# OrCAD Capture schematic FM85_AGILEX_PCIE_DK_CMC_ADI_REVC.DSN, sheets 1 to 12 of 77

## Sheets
1 Title, Note, Rev. Hist: title: AgileX I-Series FPGA Dev Kit; rev: B; note: M17472       (M17471-100, M35170-100)
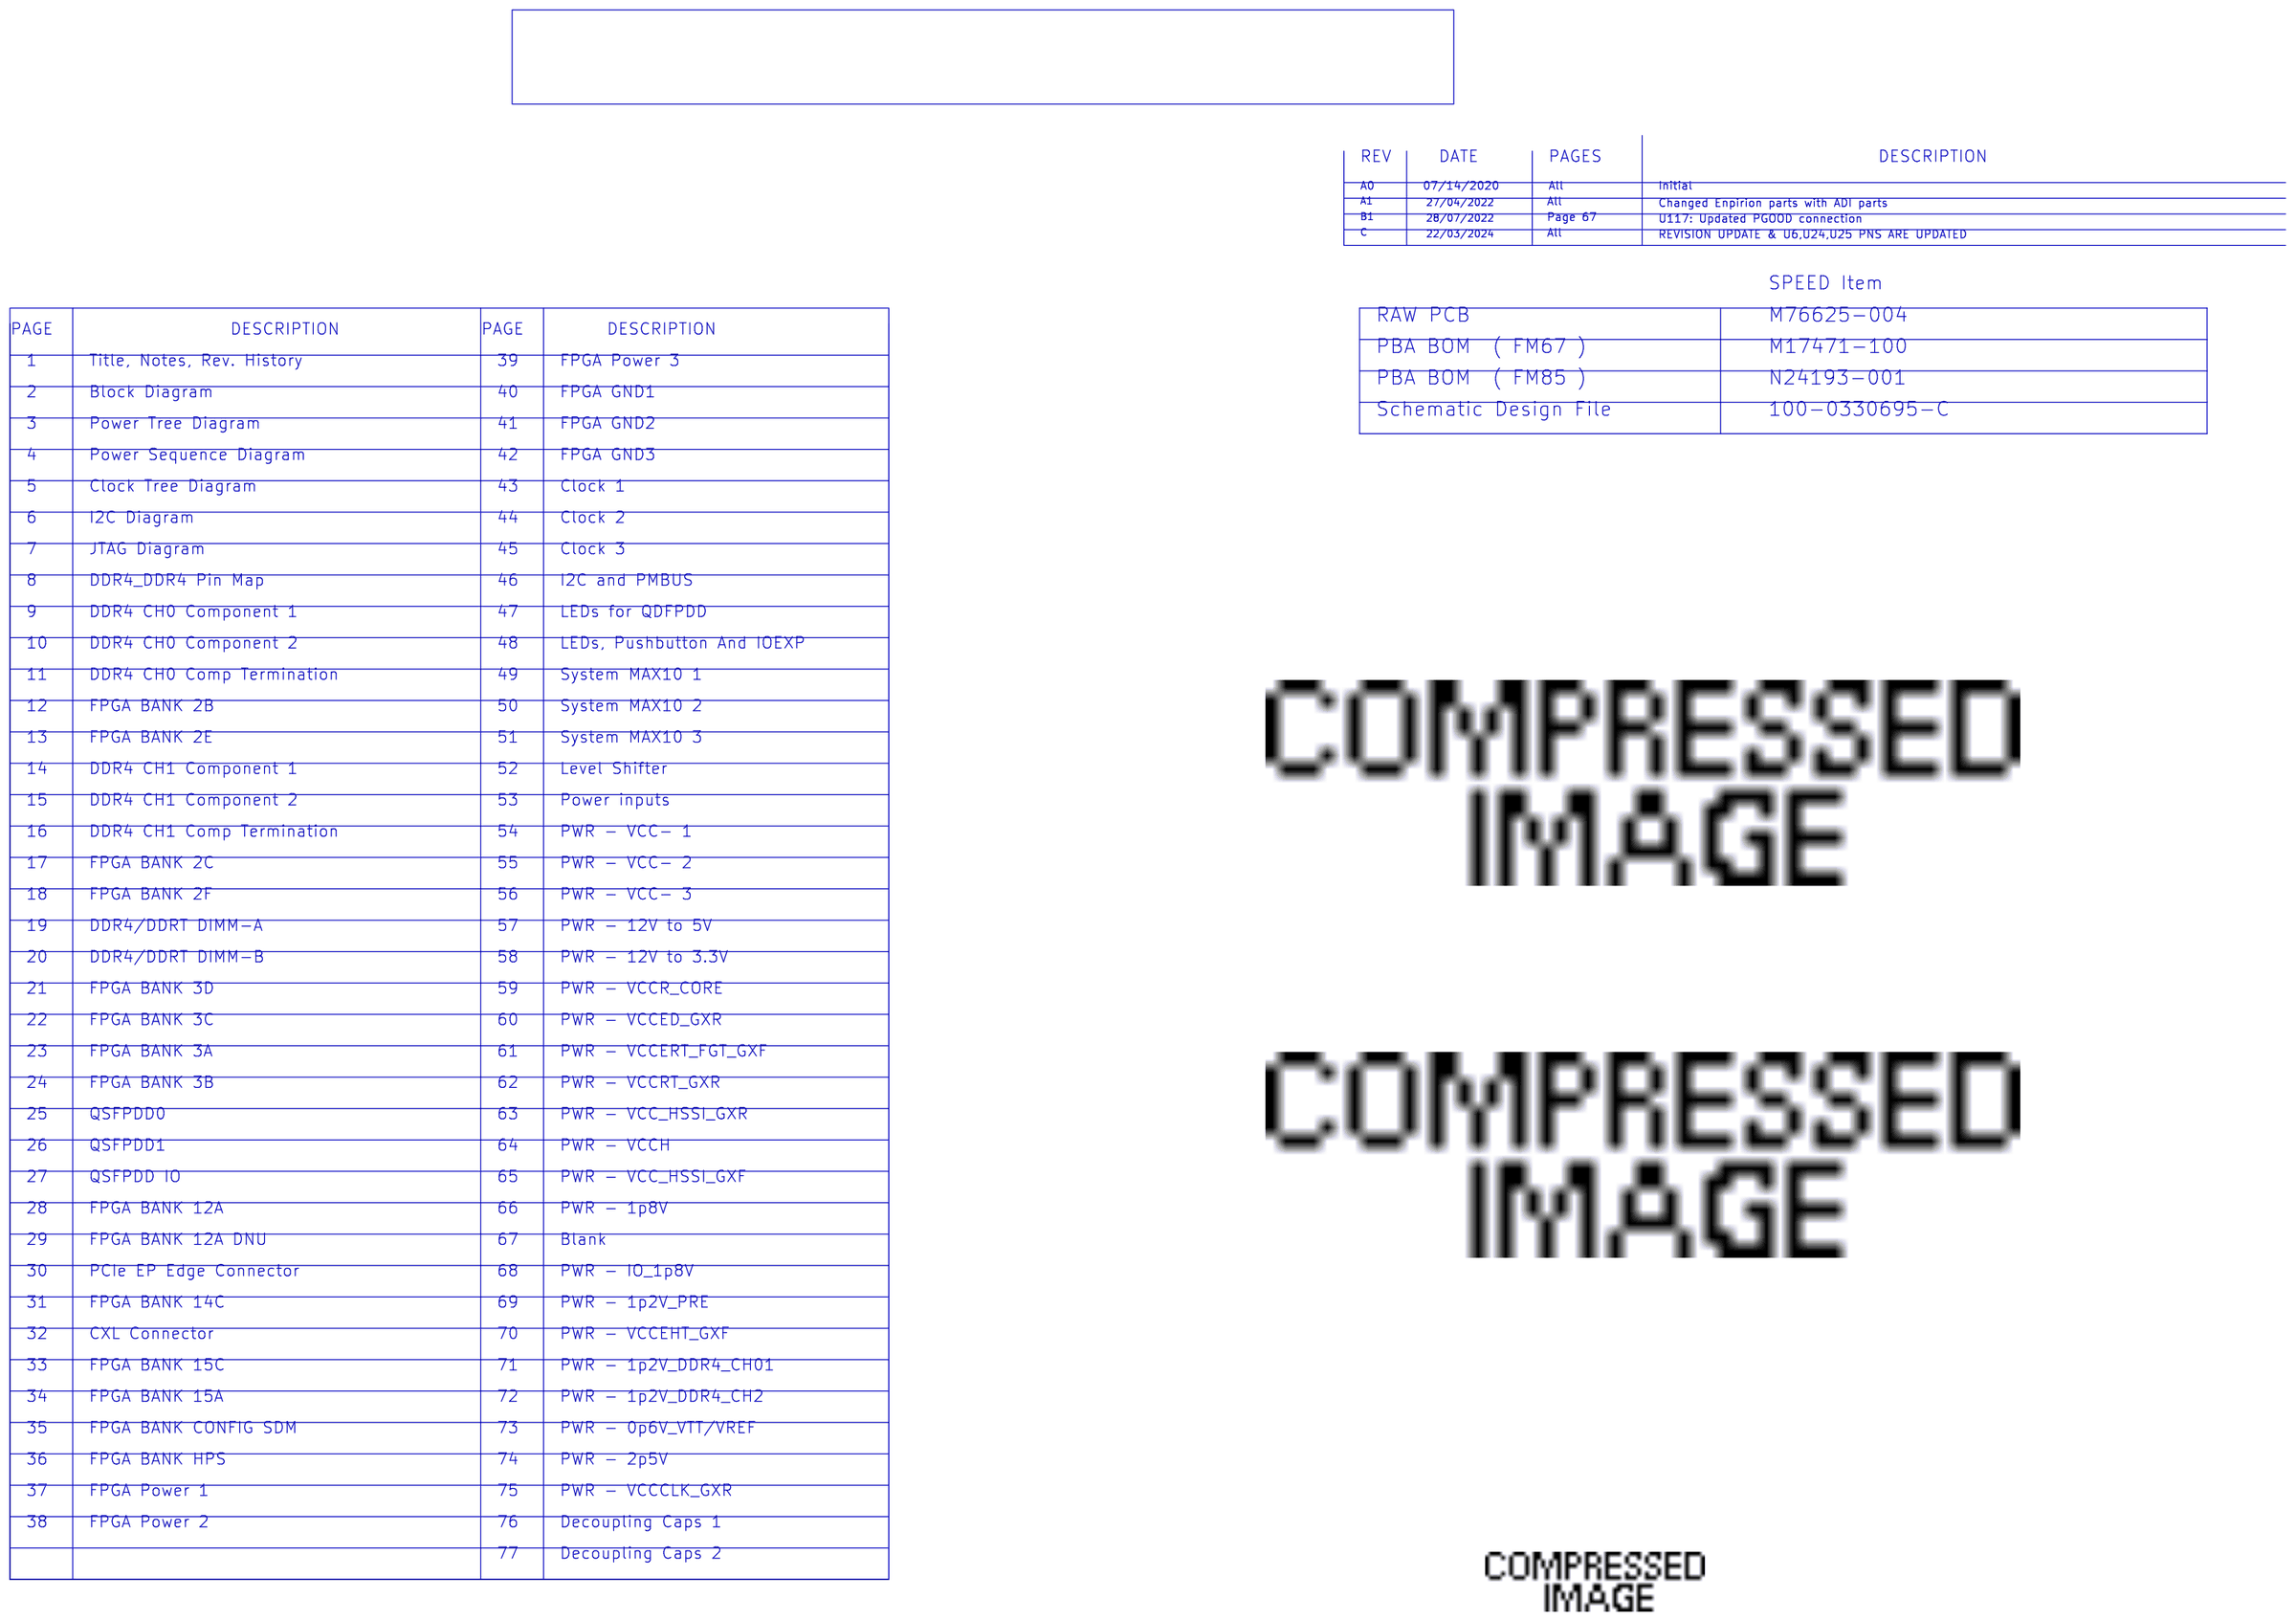
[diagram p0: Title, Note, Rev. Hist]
2 Block Diagram
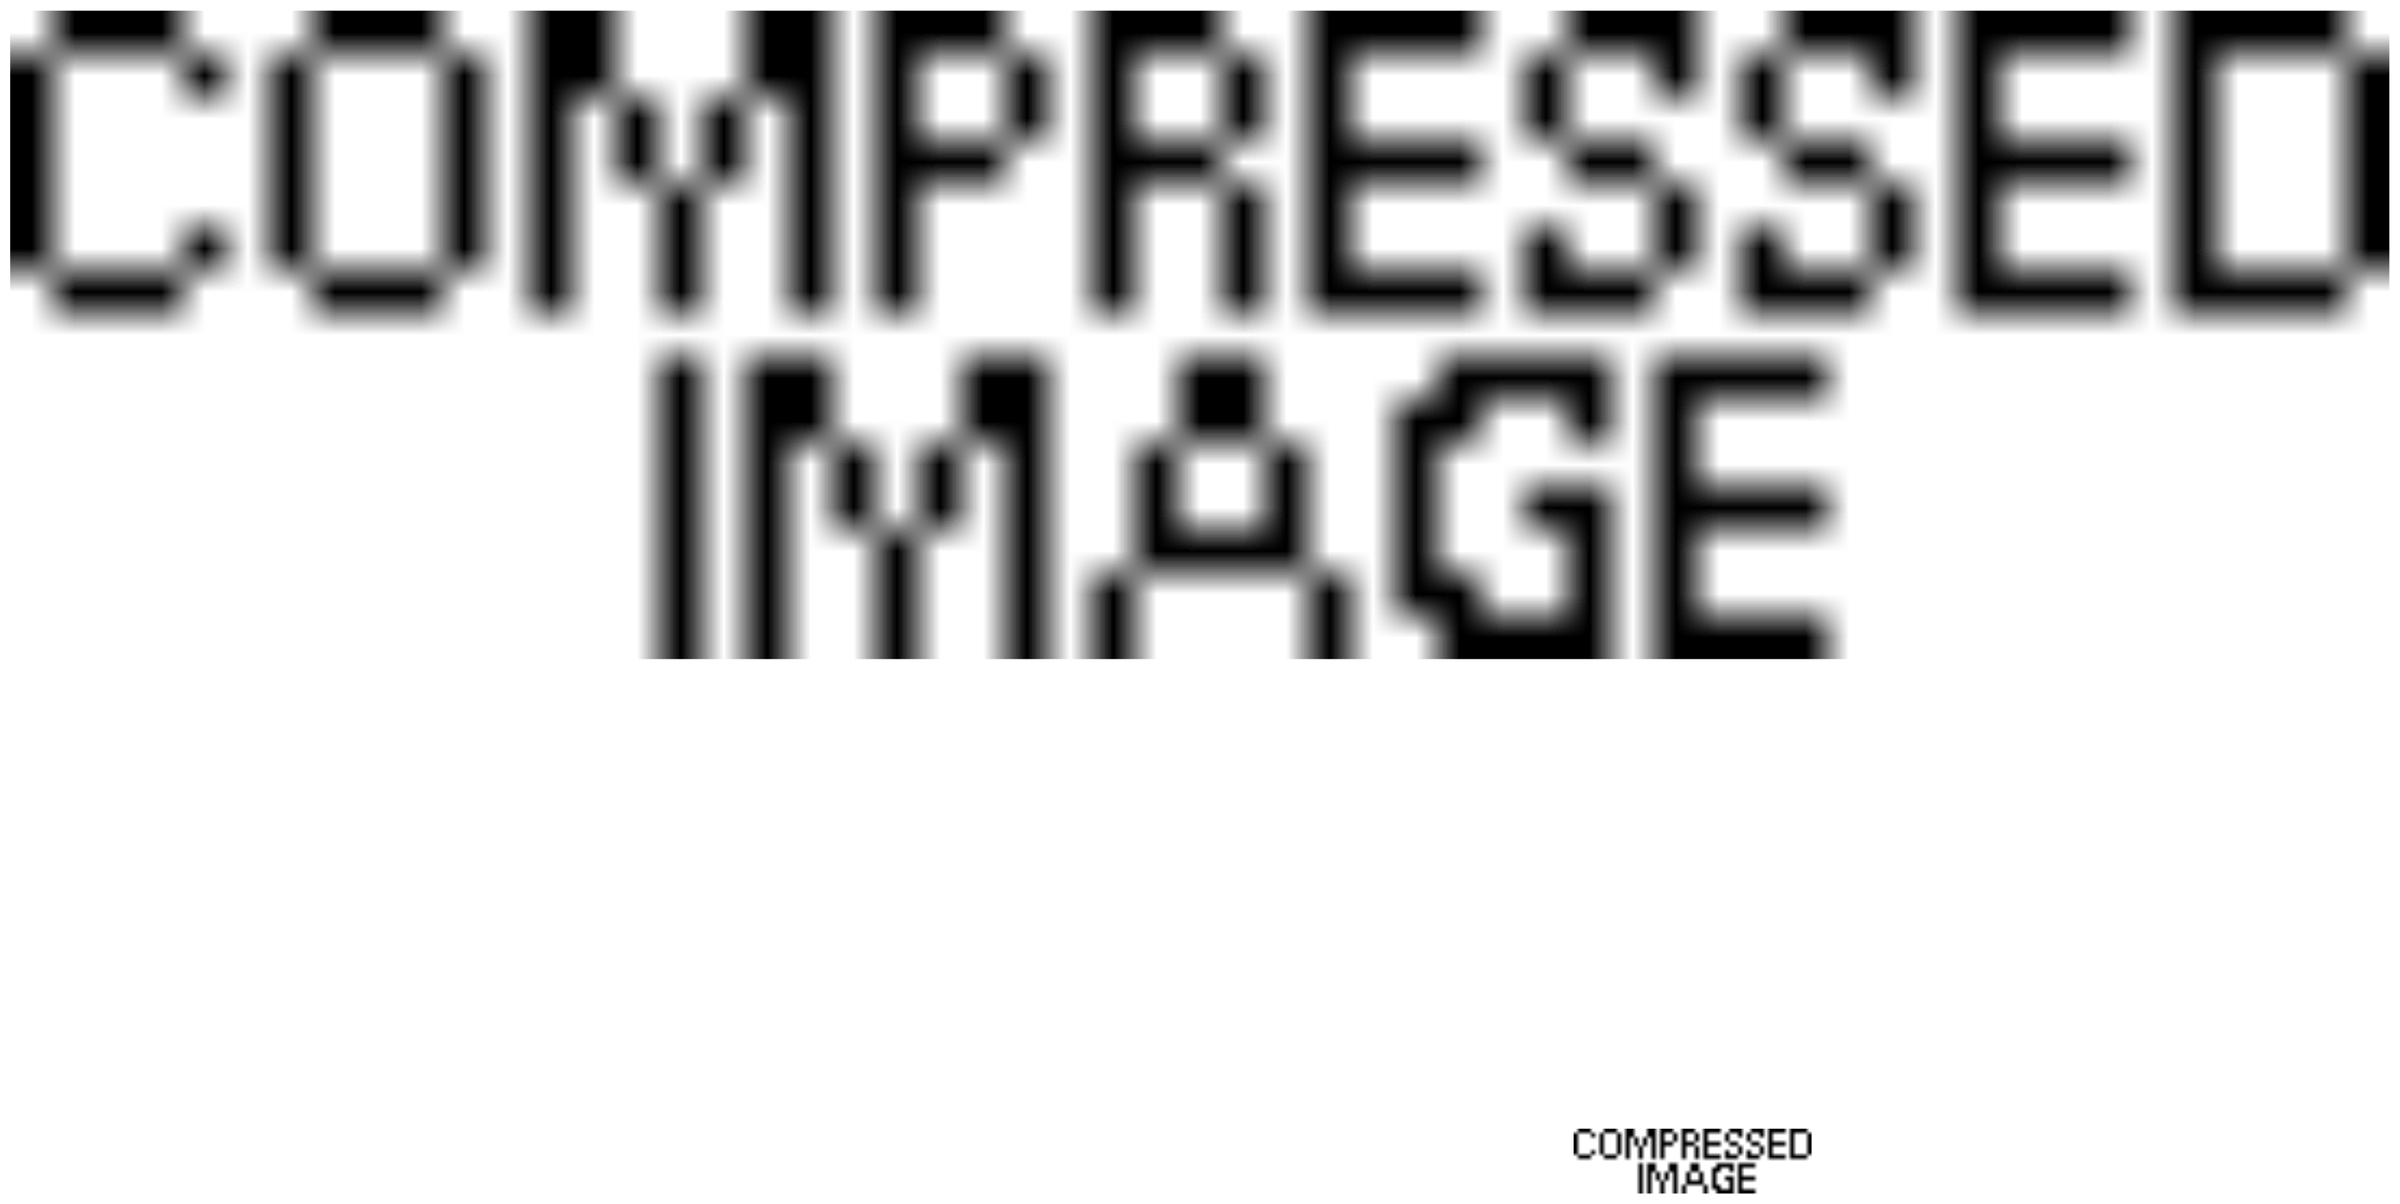
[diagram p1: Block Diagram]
3 Power Tree
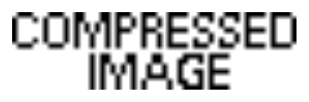
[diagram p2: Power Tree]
4 Power Sequence Diagram
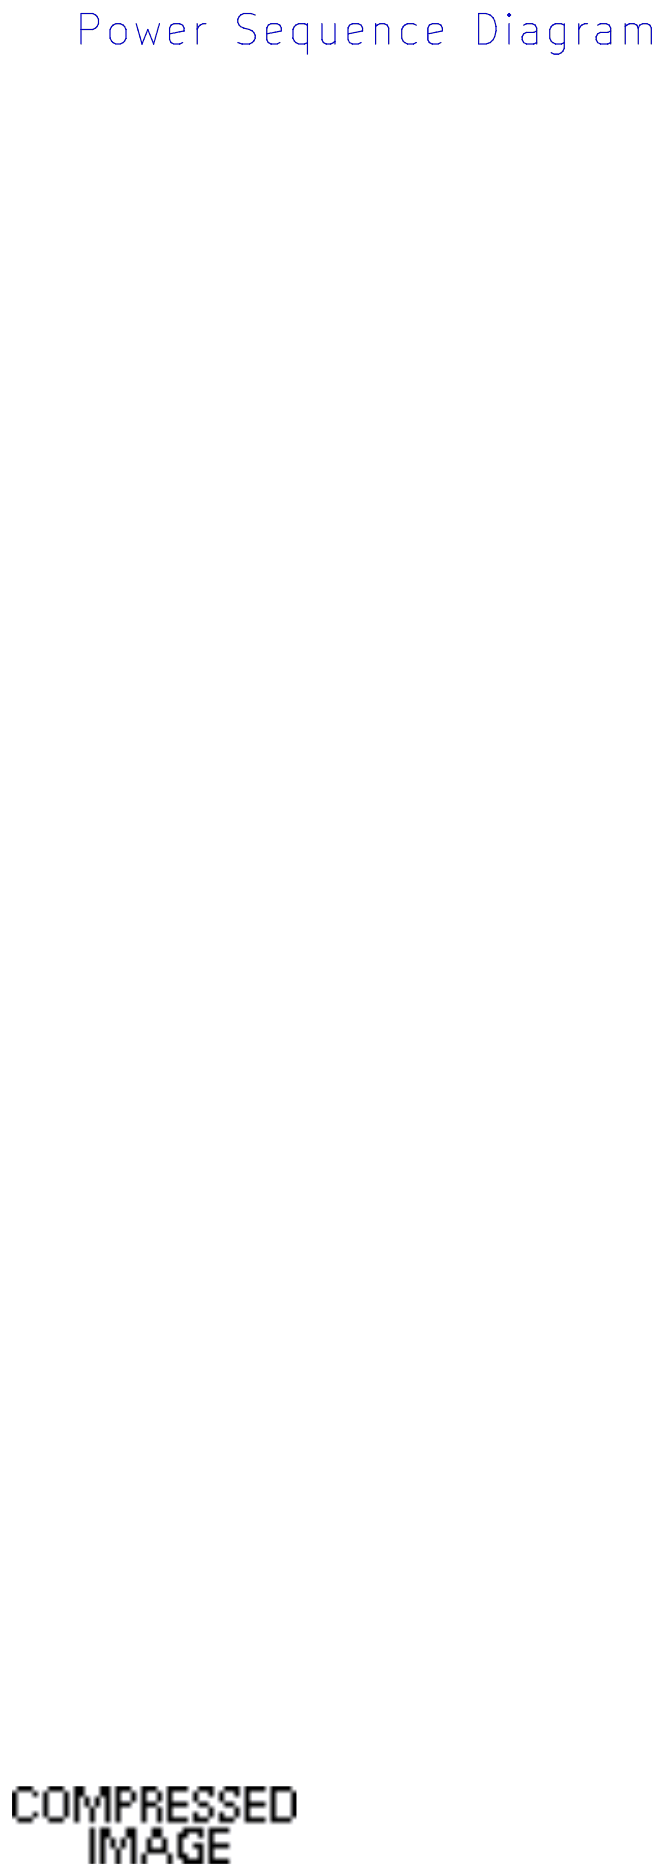
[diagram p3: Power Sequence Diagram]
5 Clock Tree Diagram
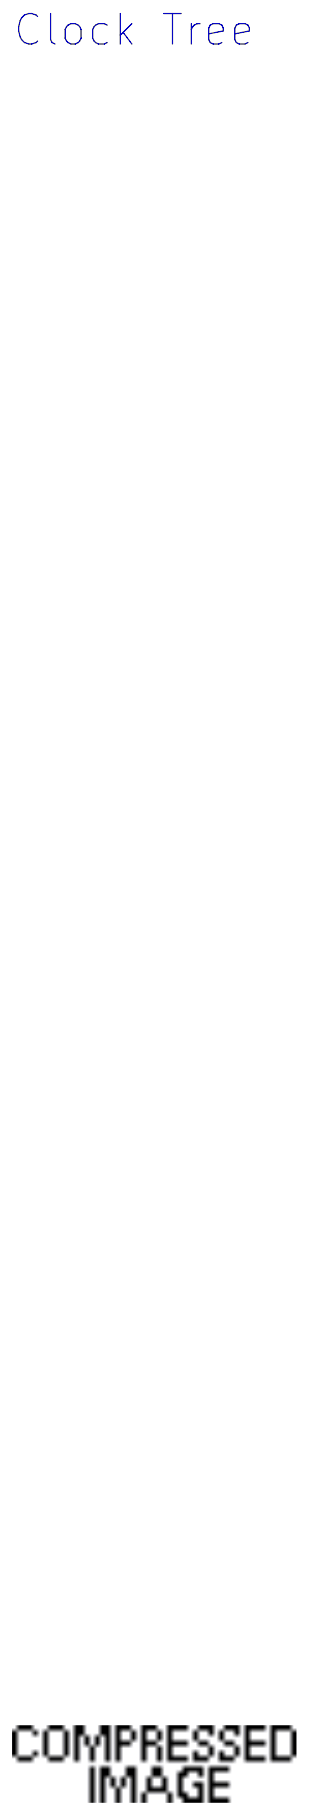
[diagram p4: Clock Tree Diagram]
6 I2C Diagram
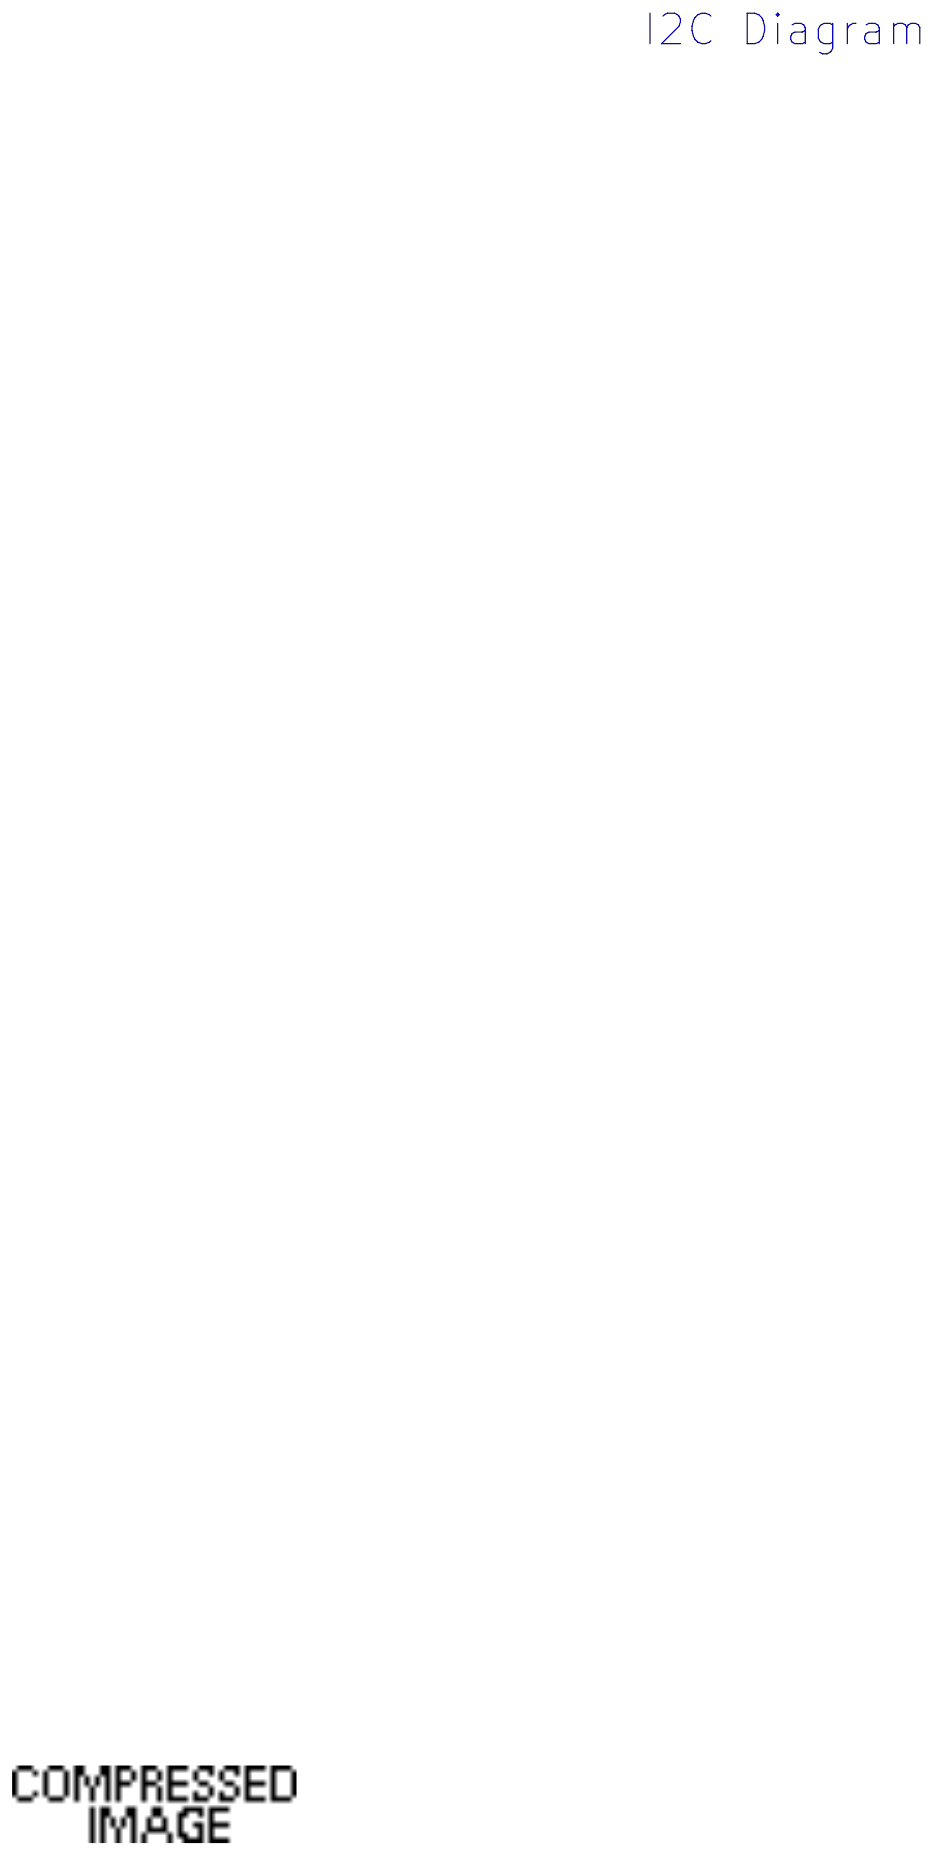
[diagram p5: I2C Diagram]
7 JTAG Diagram
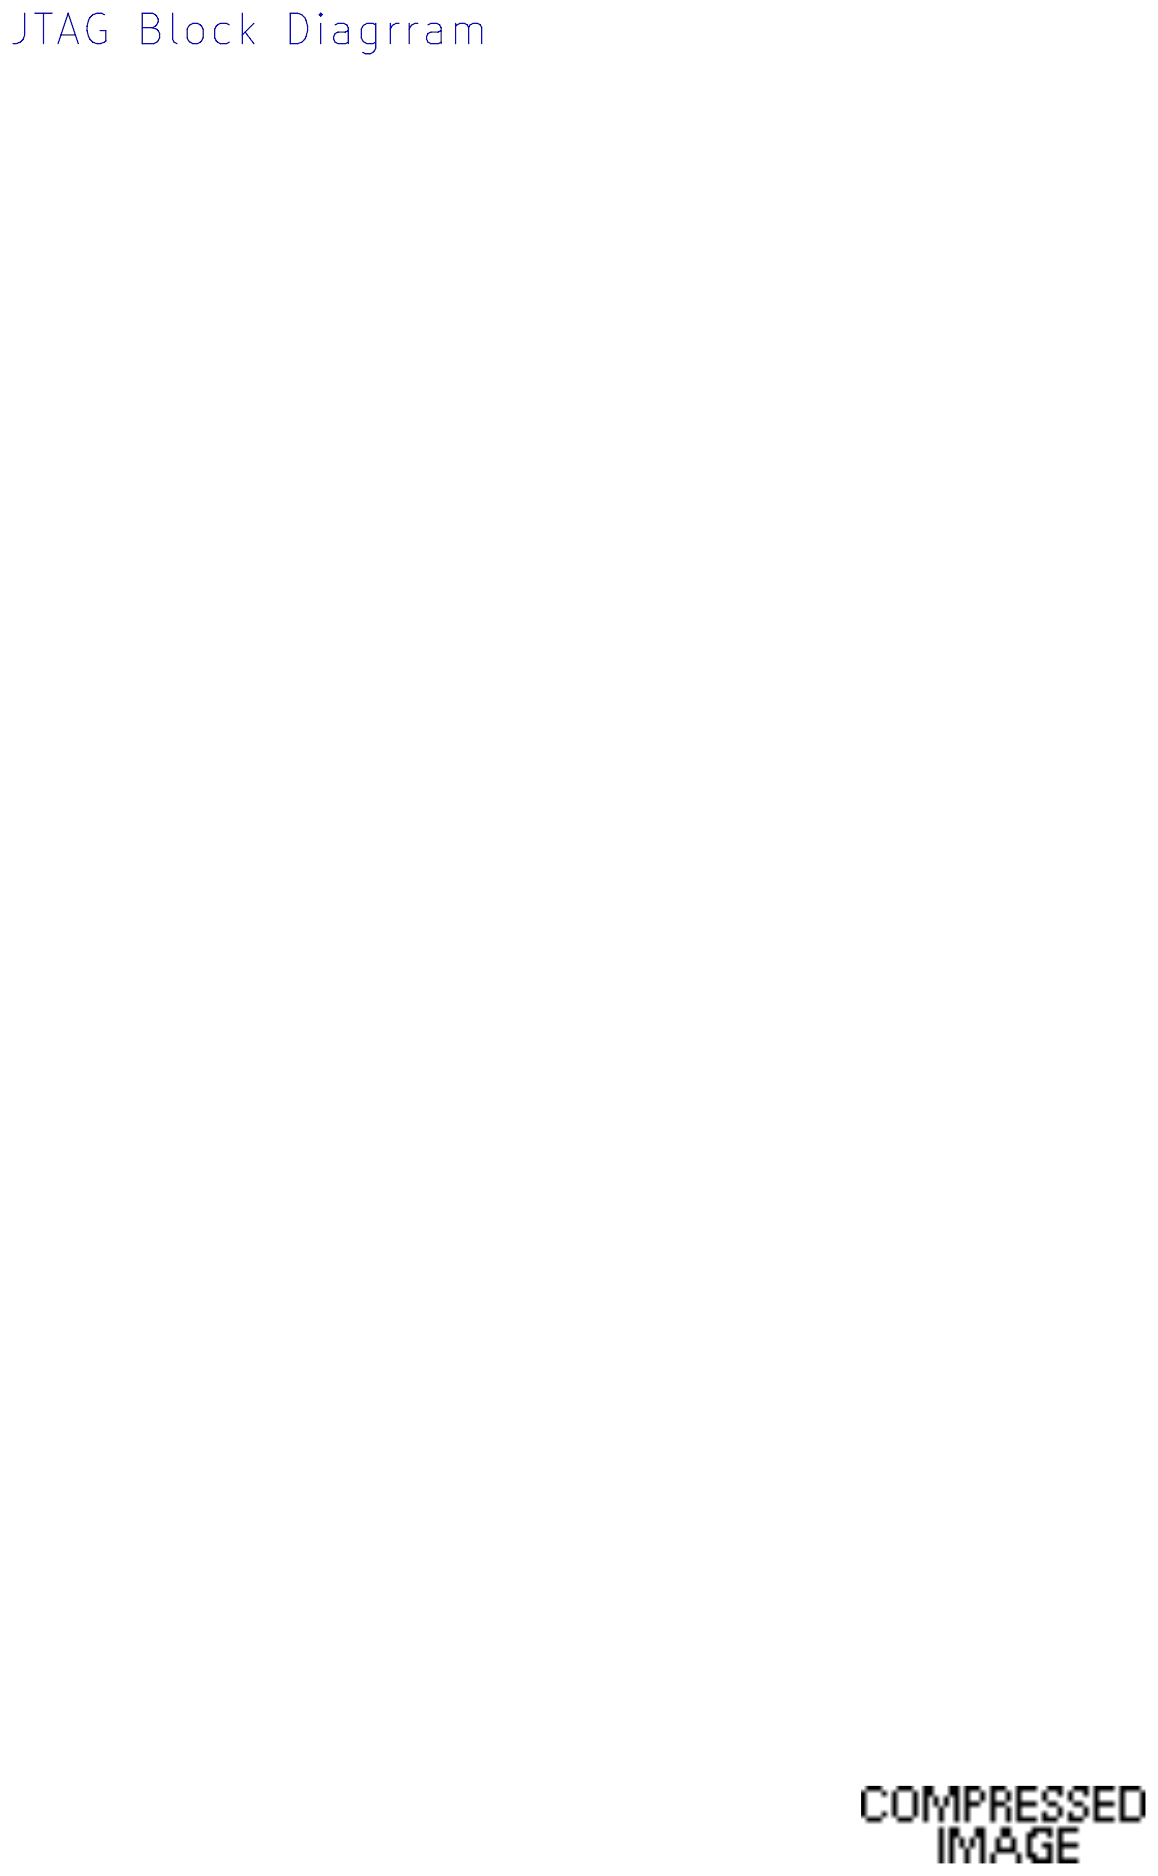
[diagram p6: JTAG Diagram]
8 DDR4_DDRT Pin Map
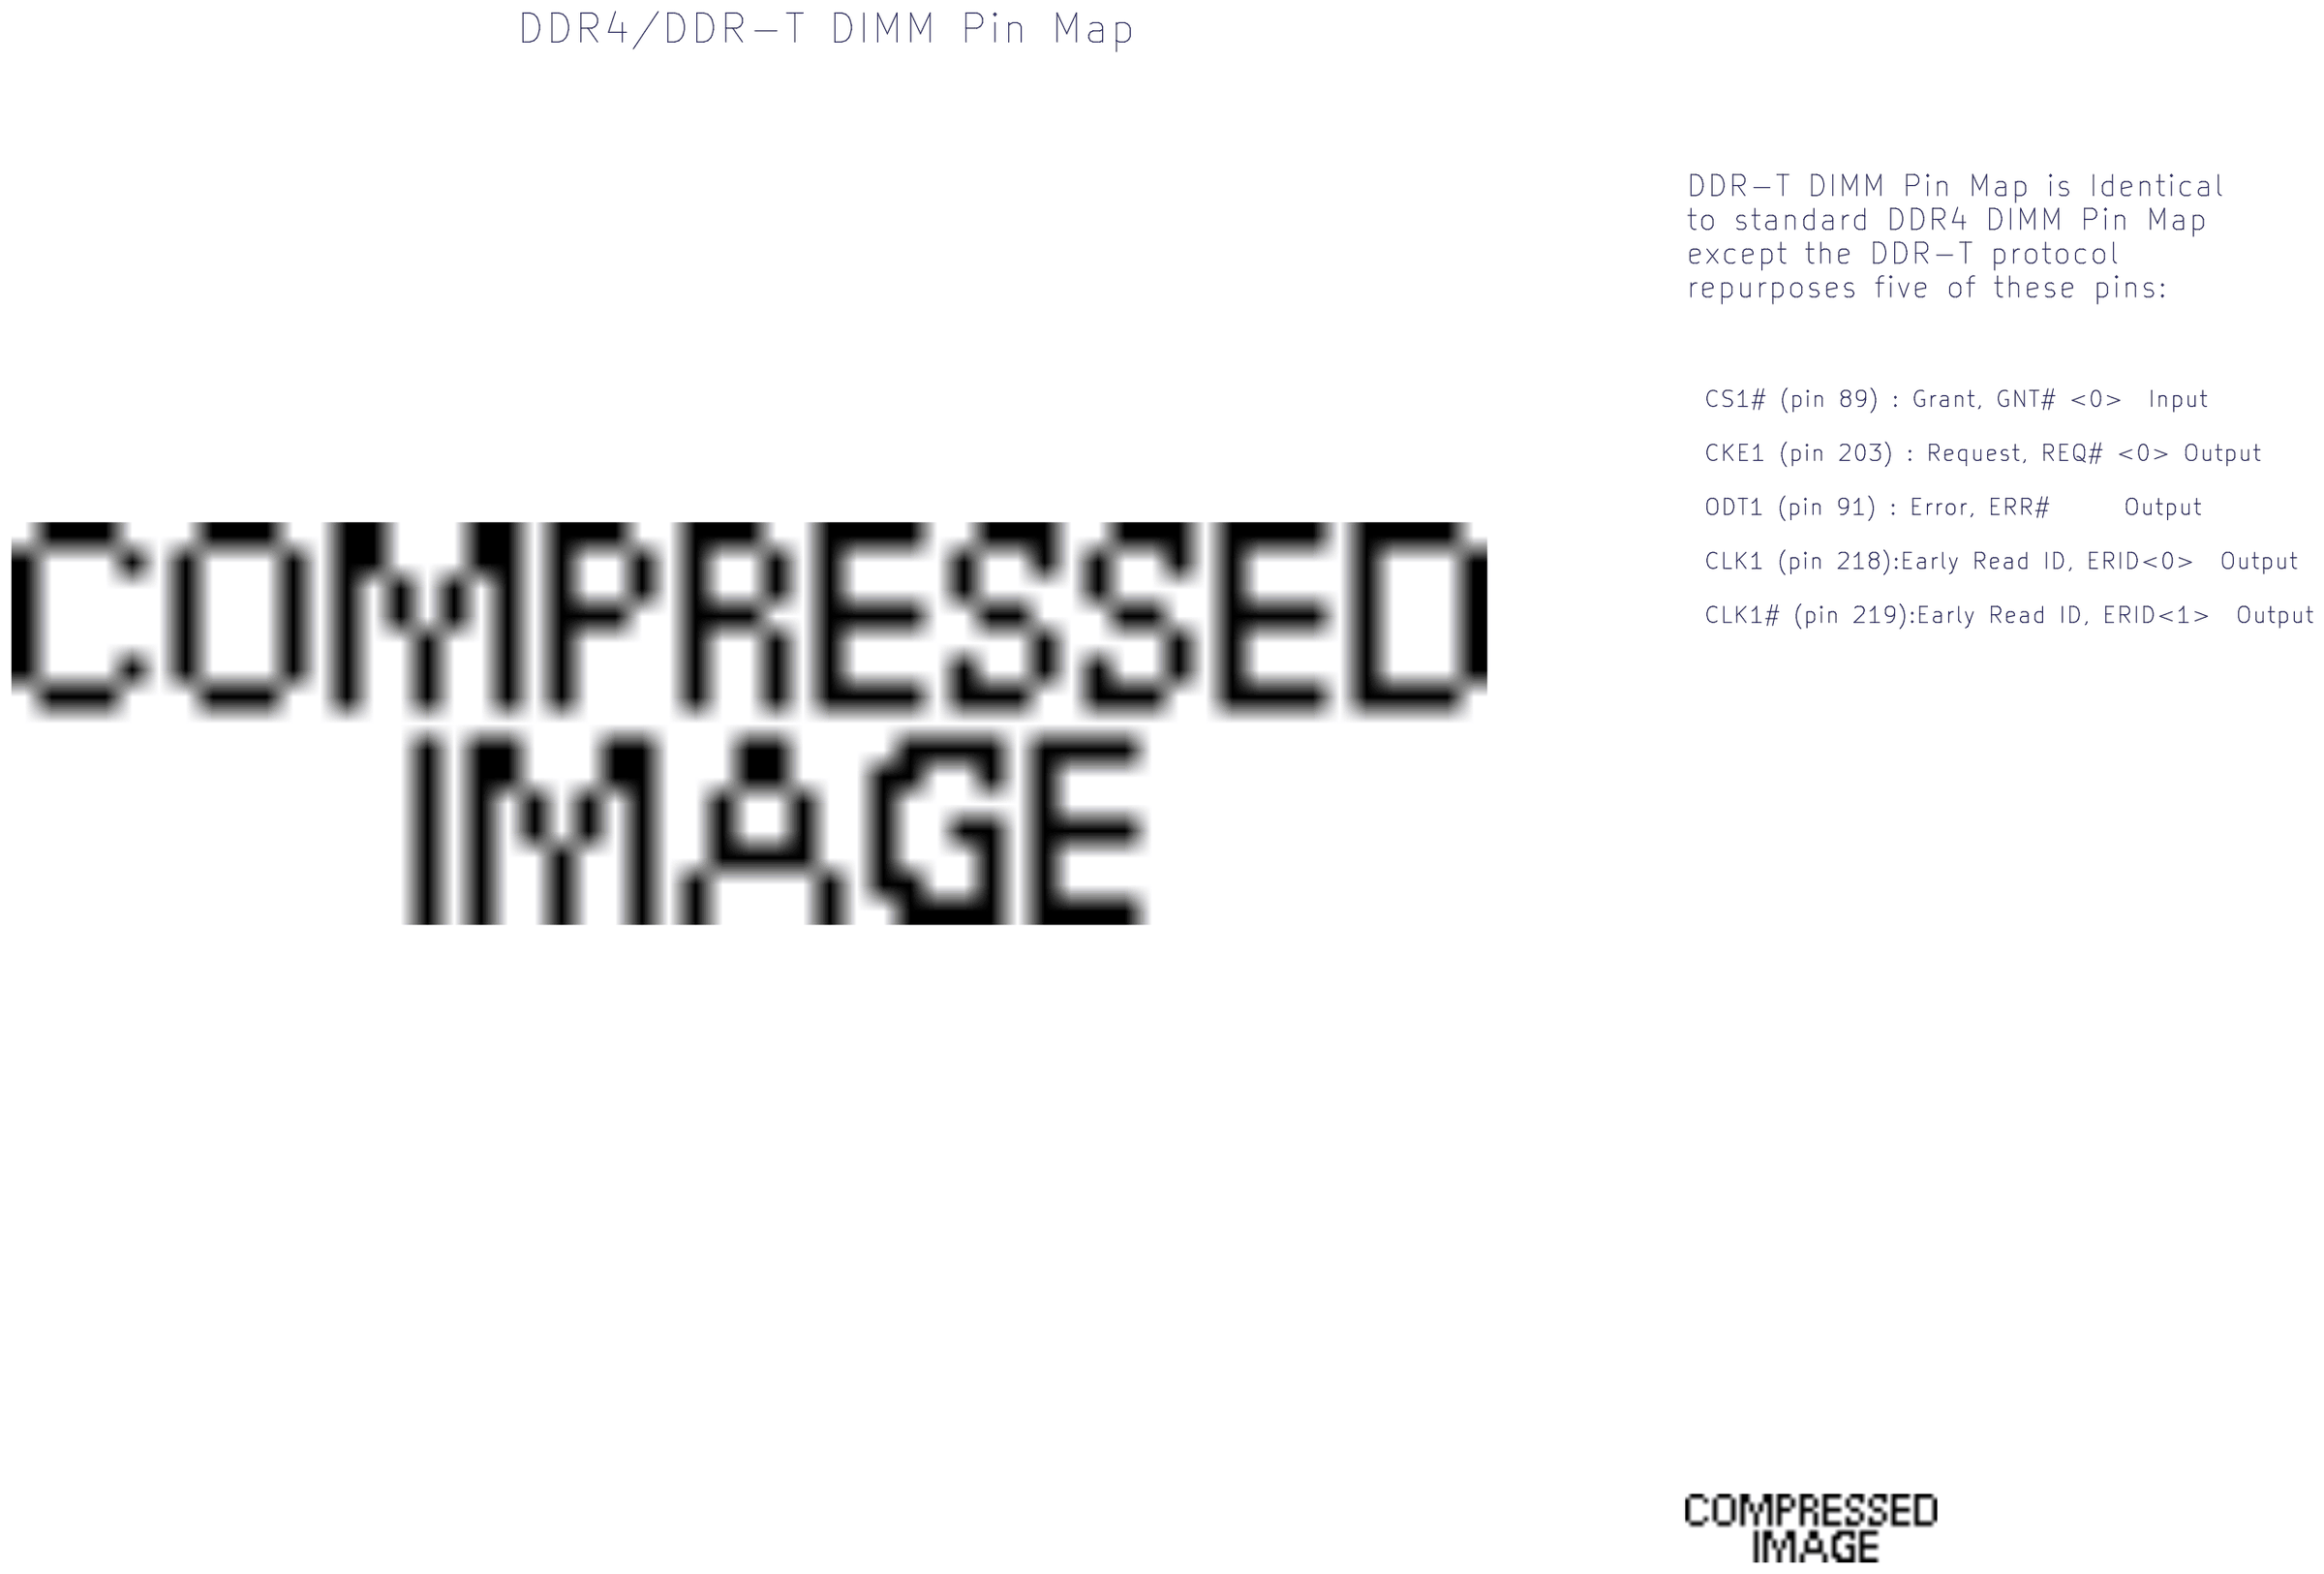
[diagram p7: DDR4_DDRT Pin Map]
9 DDR4 CH0 Component 1: size B
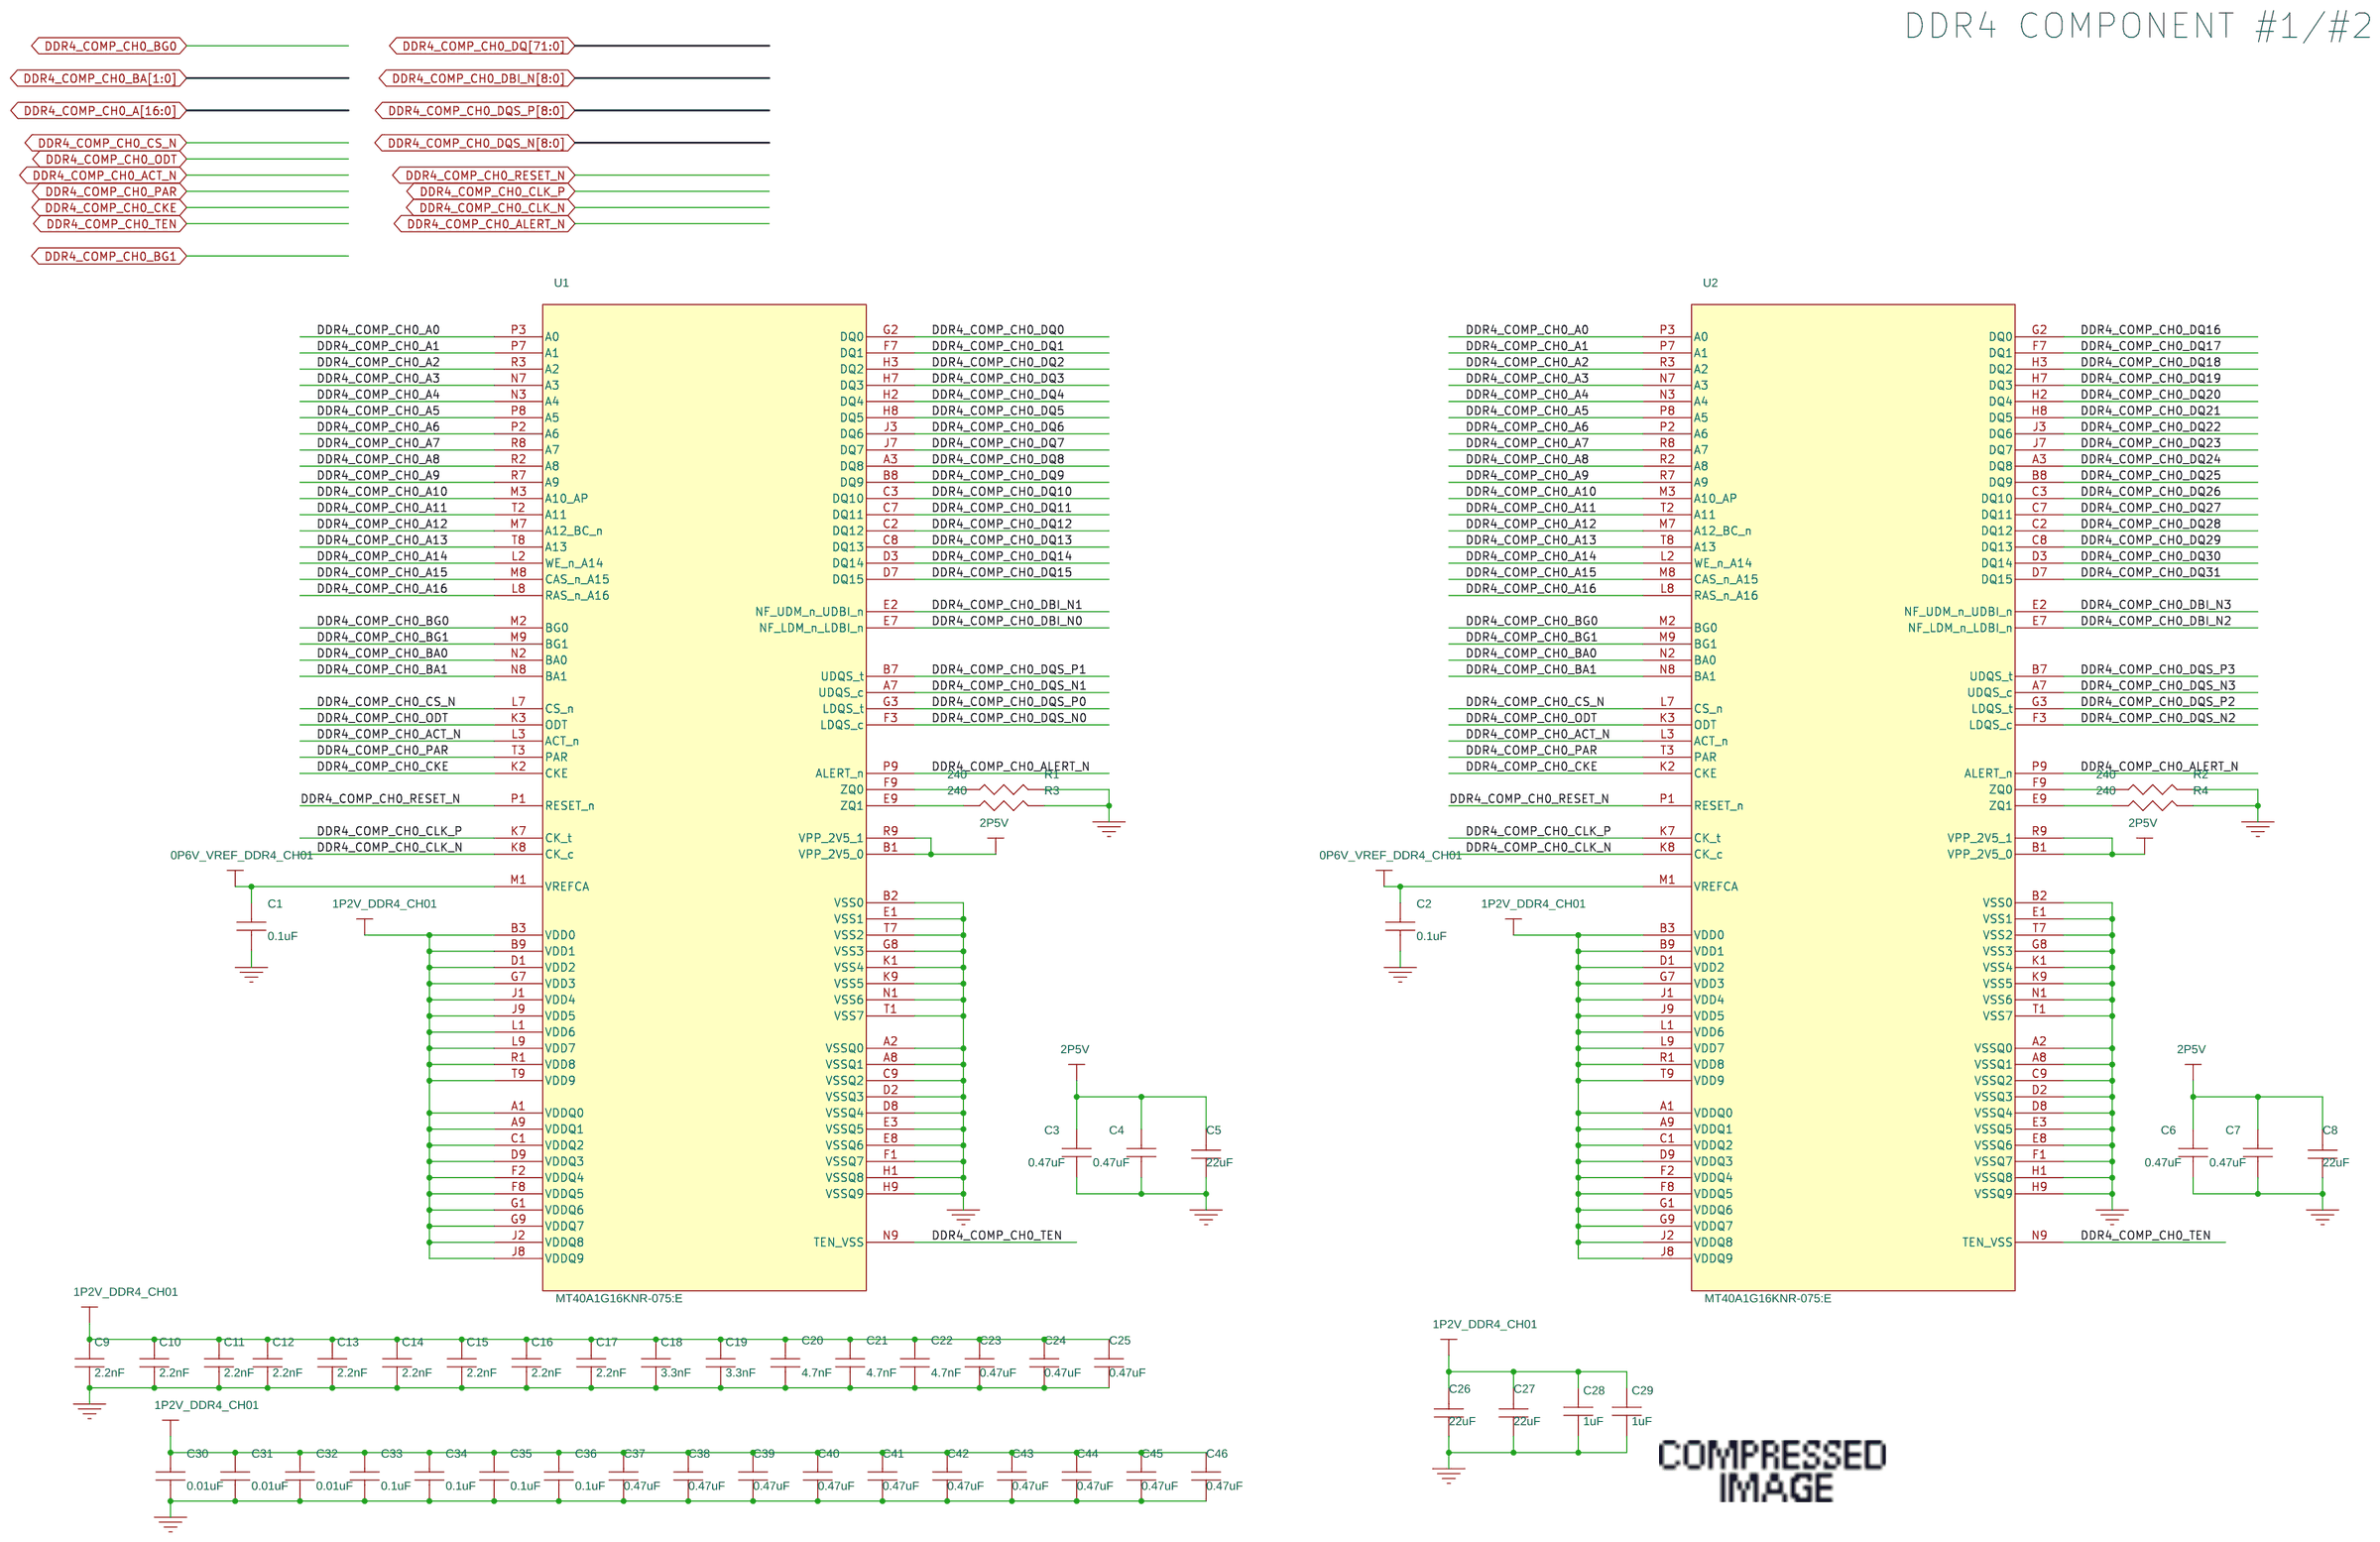
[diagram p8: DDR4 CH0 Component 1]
10 DDR4 CH0 Component 2: size B
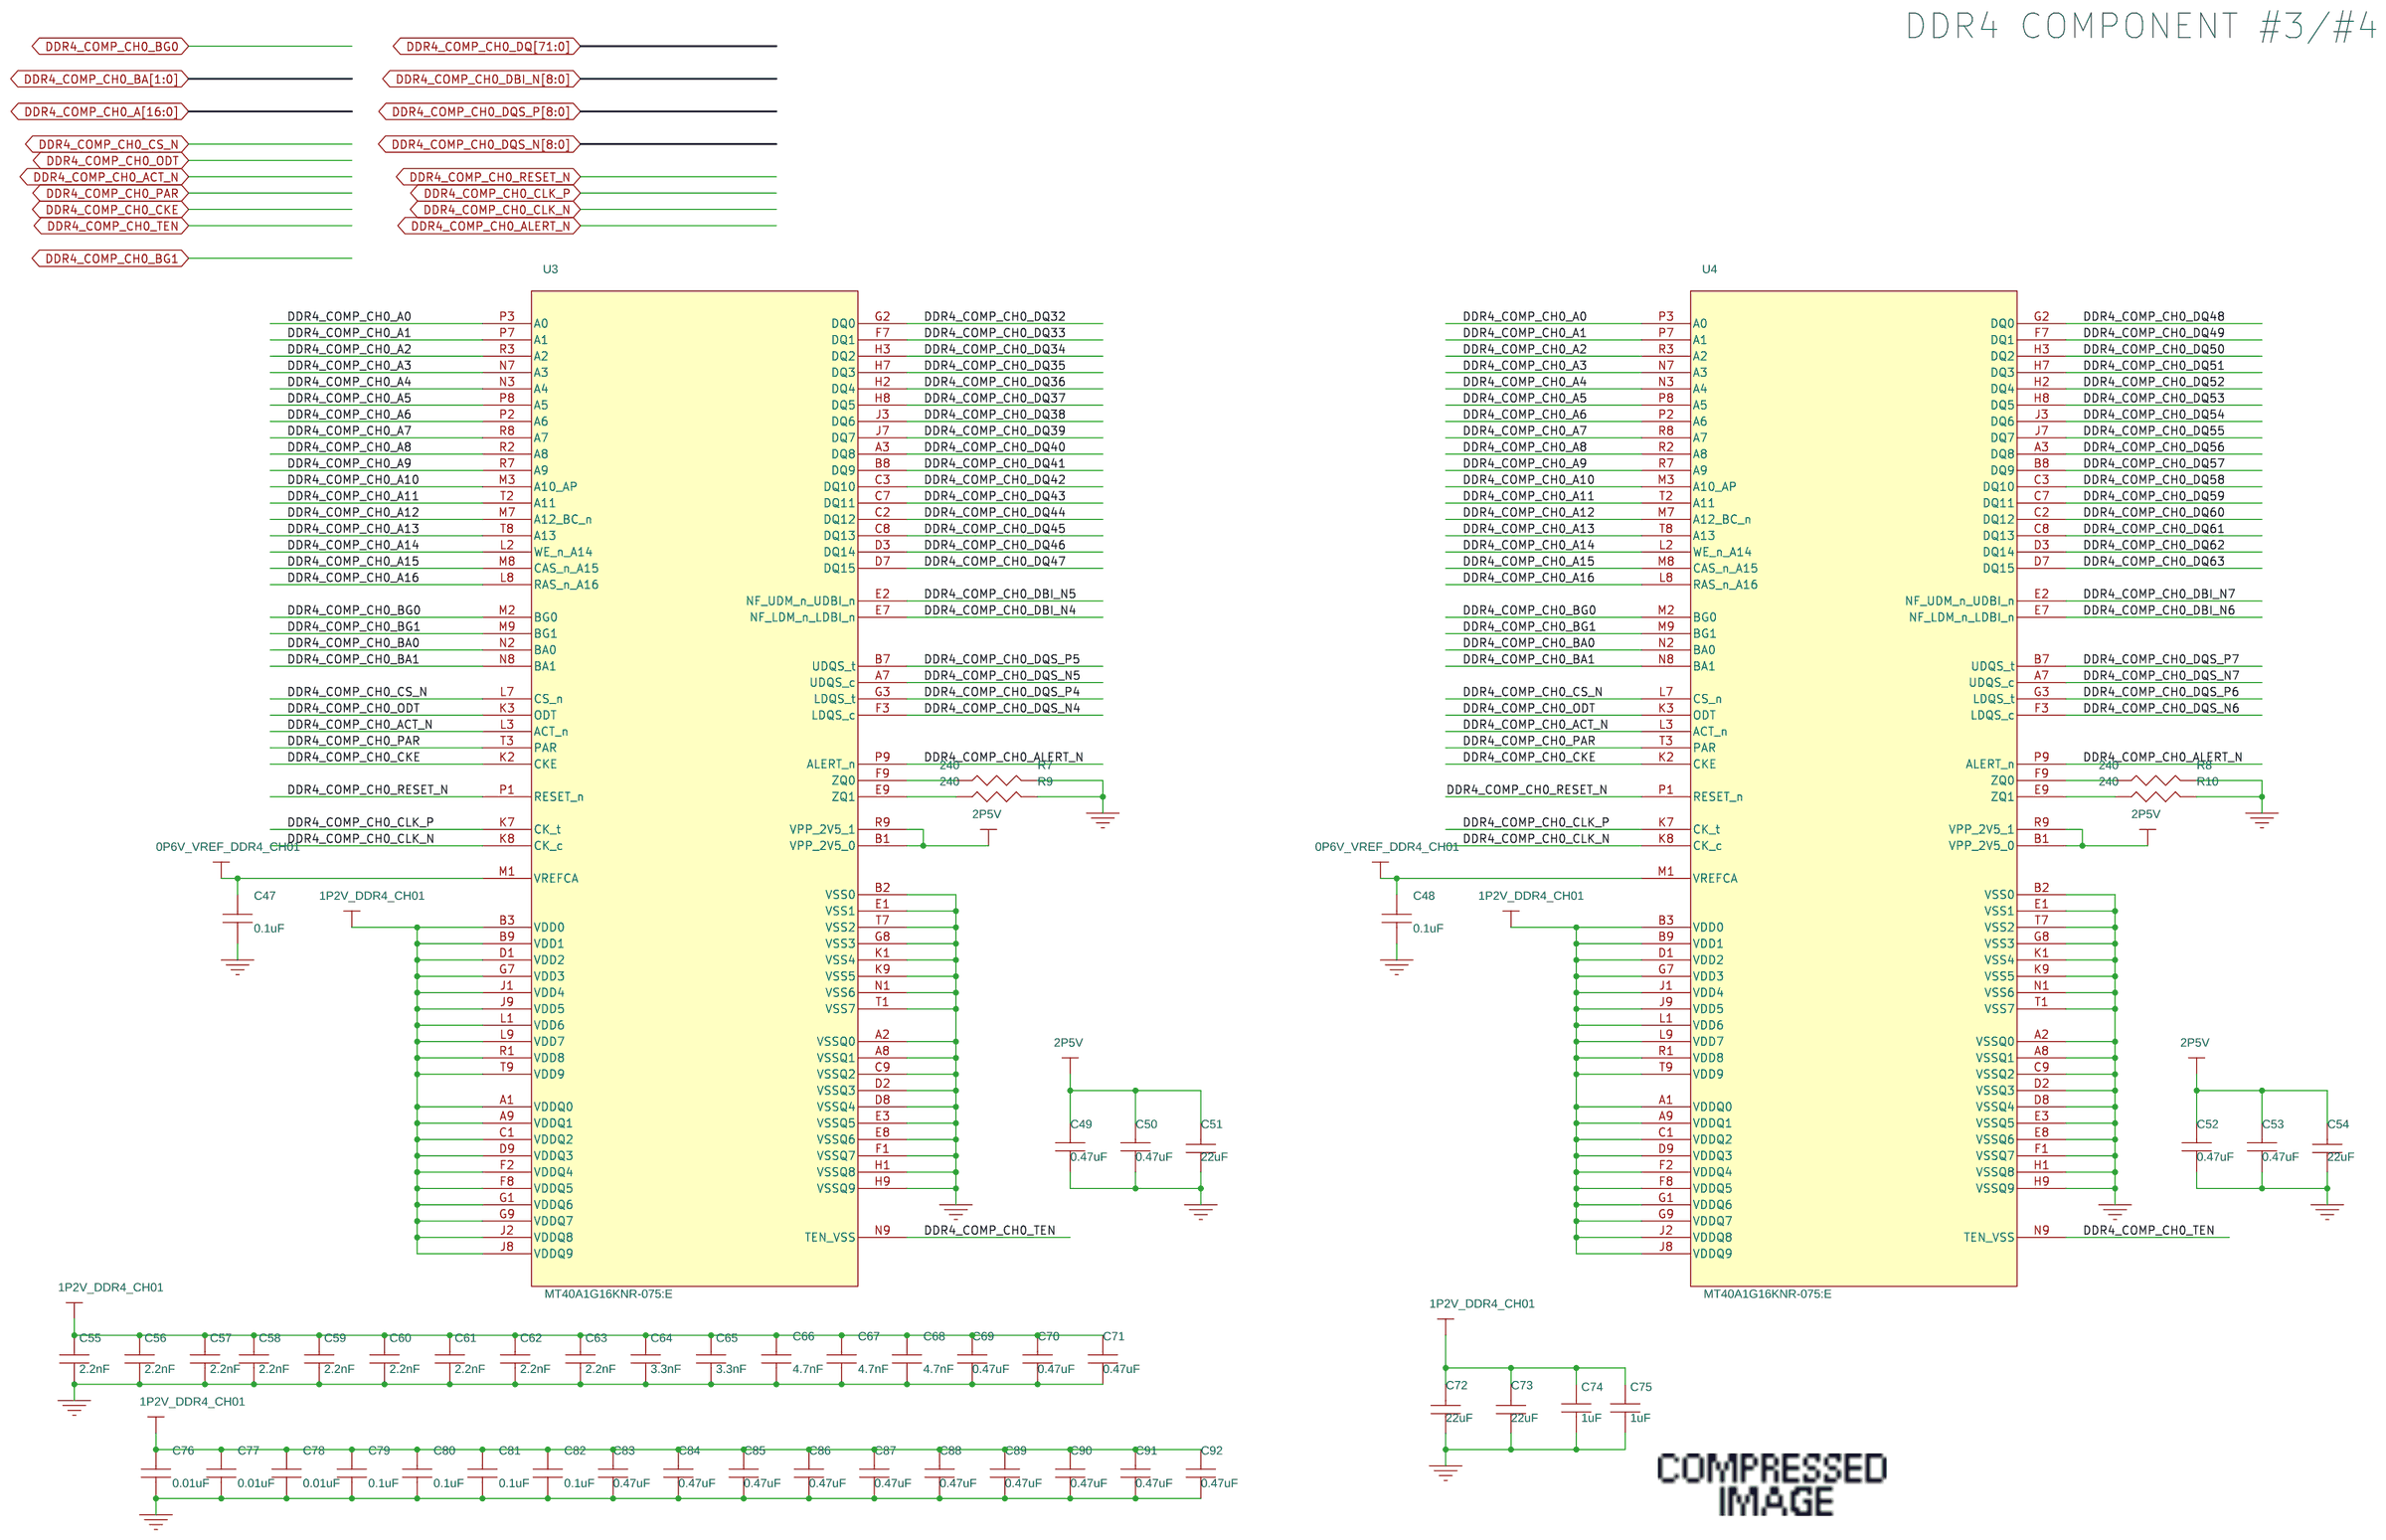
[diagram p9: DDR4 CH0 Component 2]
11 DDR4 CH0 Comp Termination: size B
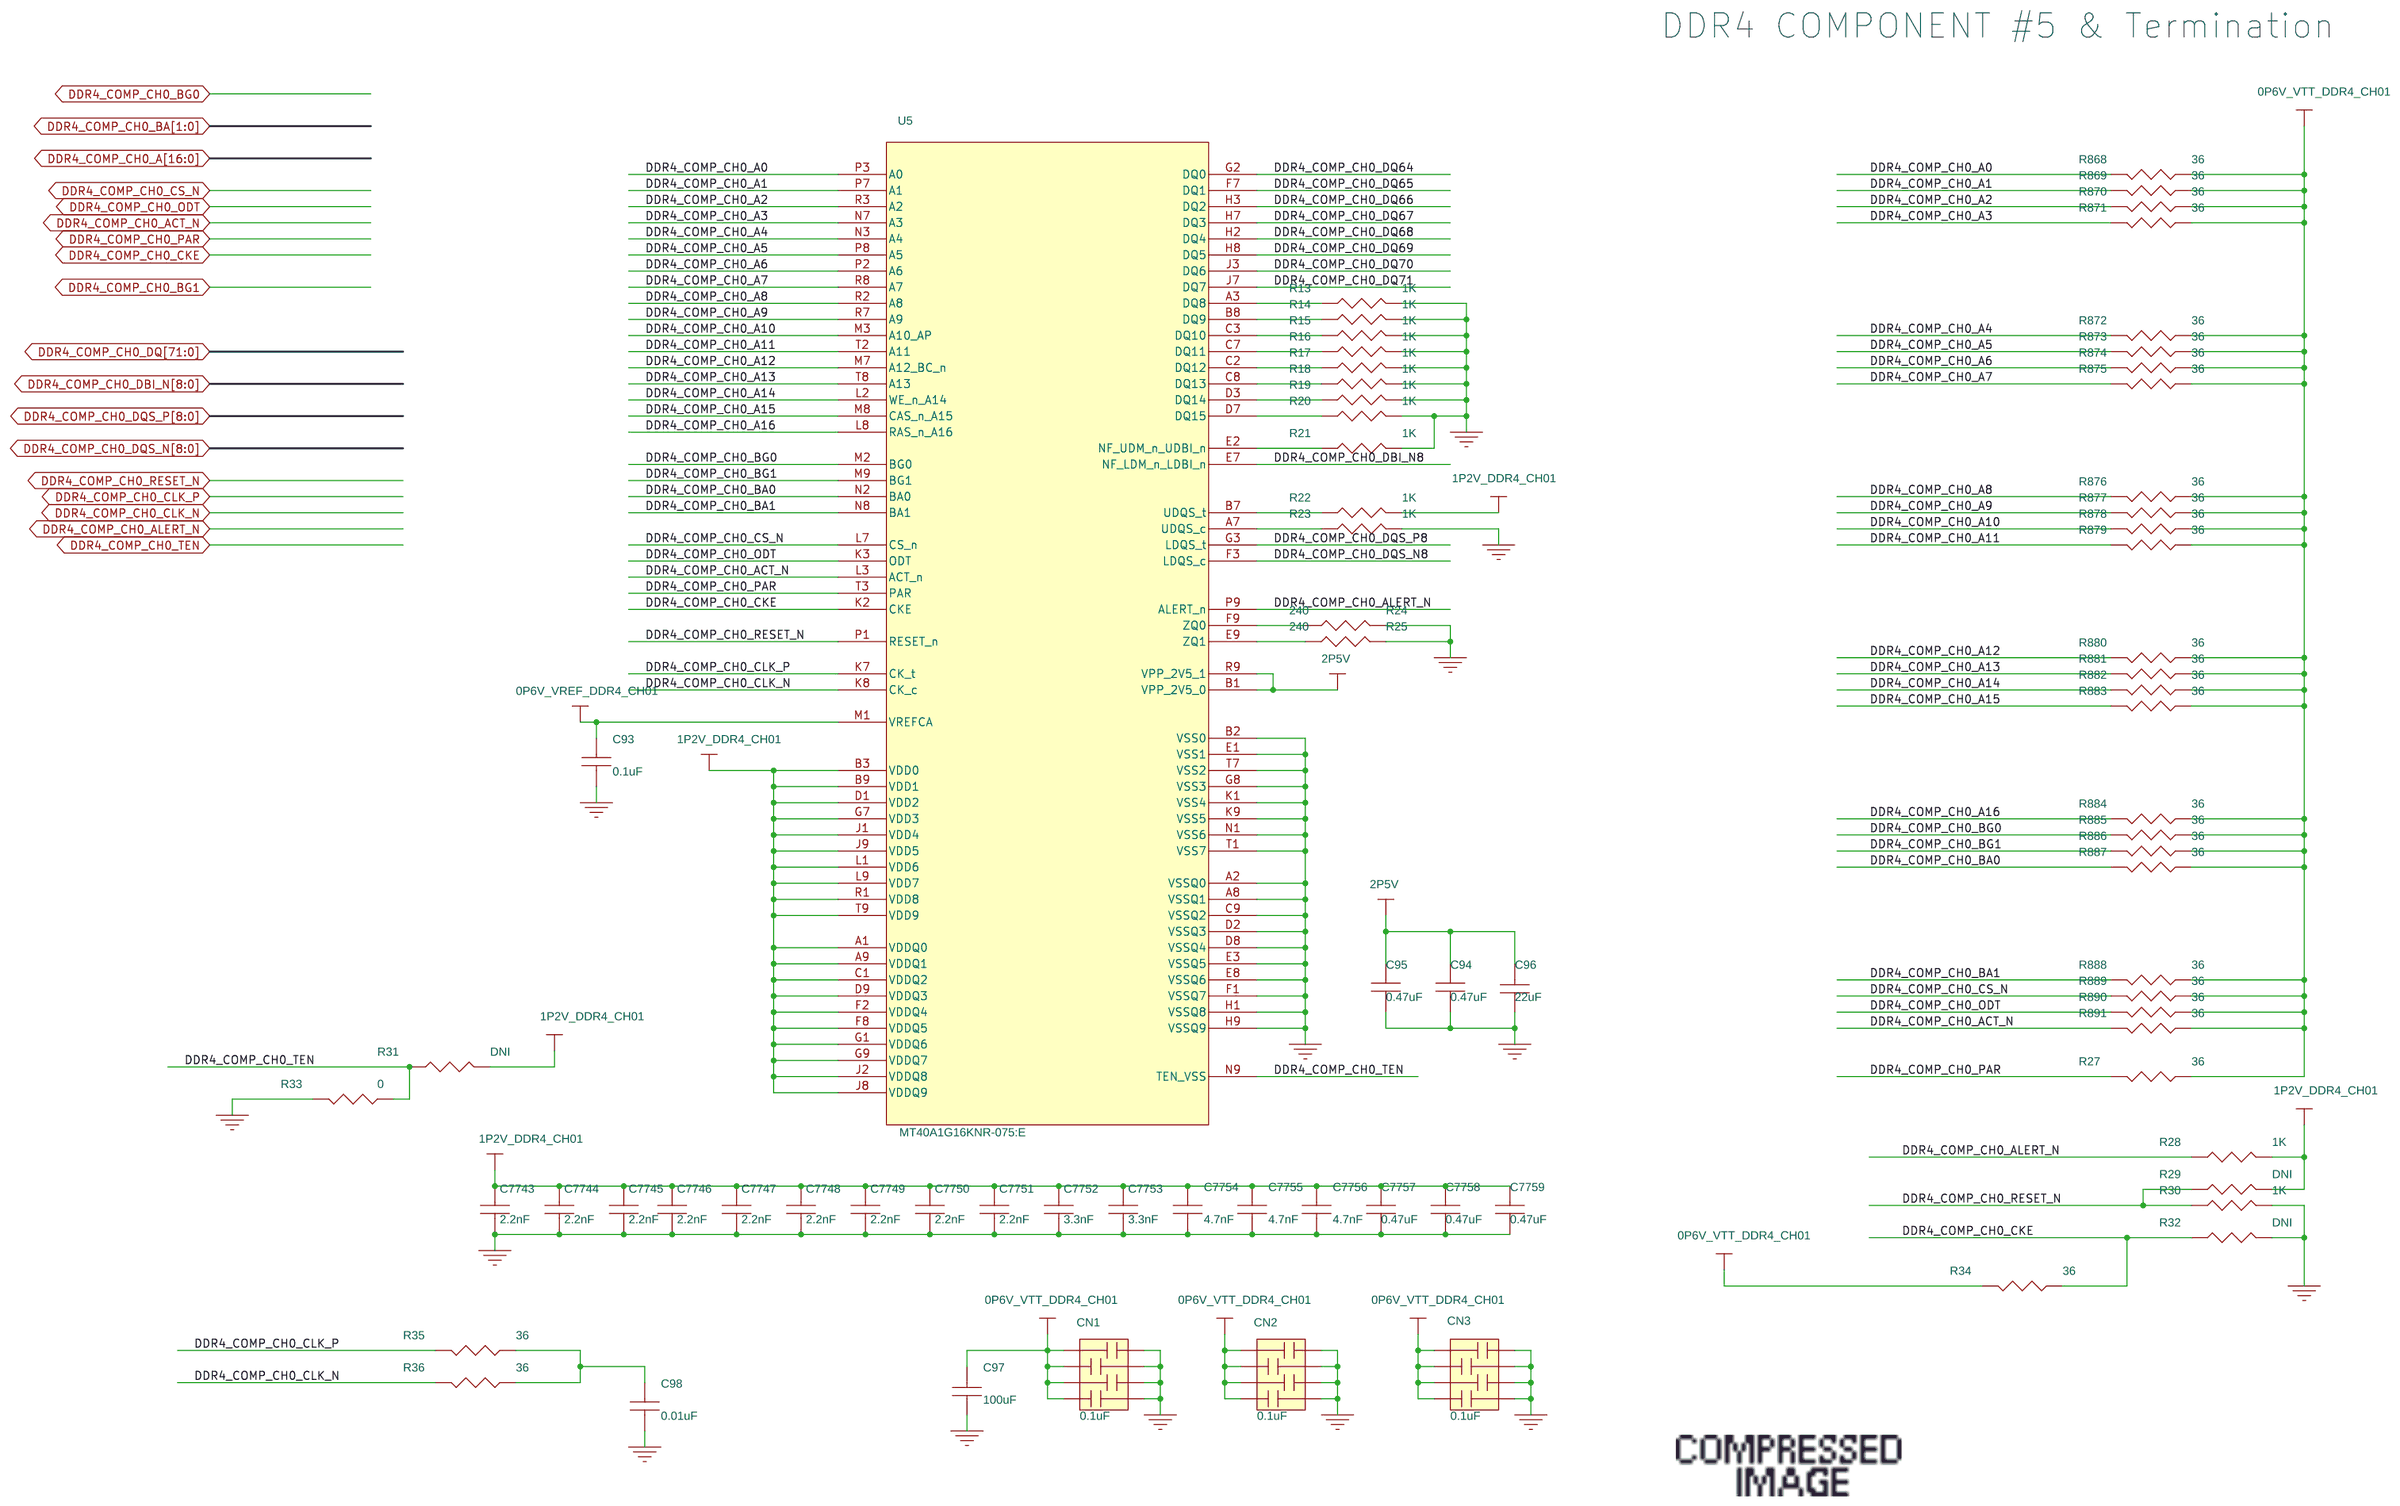
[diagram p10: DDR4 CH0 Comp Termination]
12 FPGA BANK 2B: size B
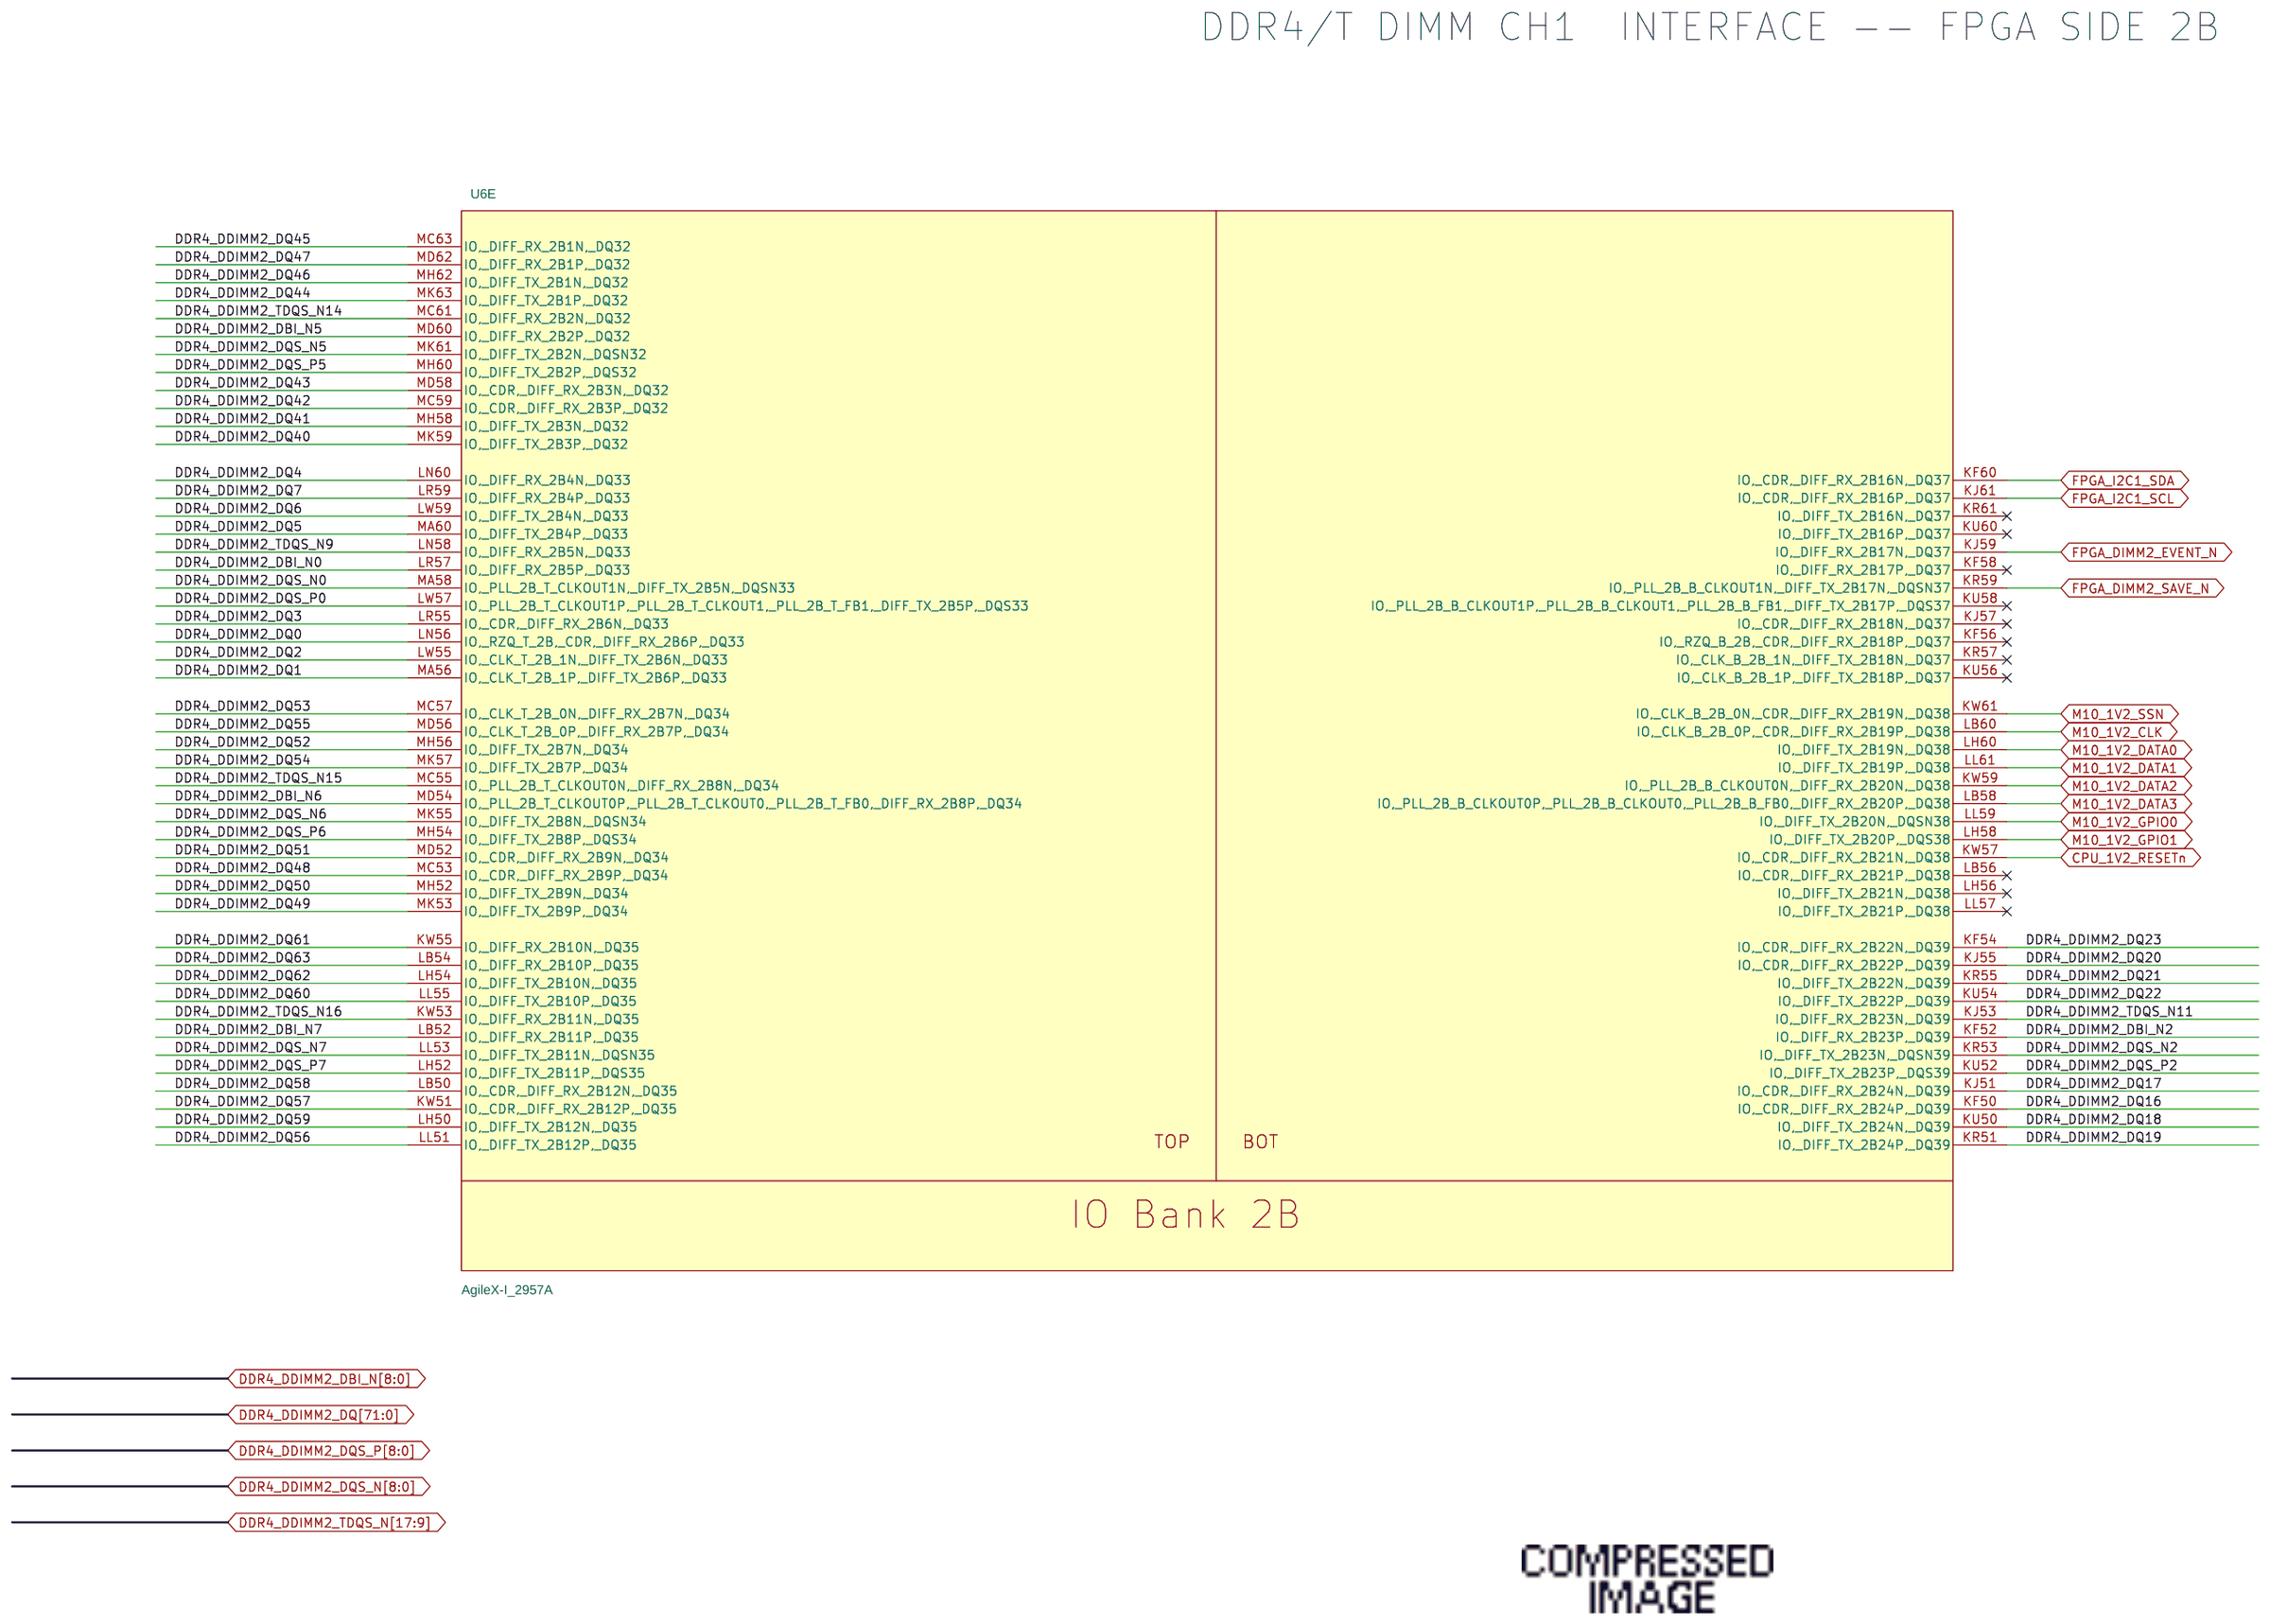
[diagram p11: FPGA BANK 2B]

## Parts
sheet DDR4 CH0 Comp Termination
C93  0.1uF  [0402]
C94  0.47uF  [0402]
C95  0.47uF  [0402]
C96  22uF  [0603]
C97  100uF  [1206]
C98  0.01uF  [0402]
C7743  2.2nF  [0402]
C7744  2.2nF  [0402]
C7745  2.2nF  [0402]
C7746  2.2nF  [0402]
C7747  2.2nF  [0402]
C7748  2.2nF  [0402]
C7749  2.2nF  [0402]
C7750  2.2nF  [0402]
C7751  2.2nF  [0402]
C7752  3.3nF  [0402]
C7753  3.3nF  [0402]
C7754  4.7nF  [0402]
C7755  4.7nF  [0402]
C7756  4.7nF  [0402]
C7757  0.47uF  [0402]
C7758  0.47uF  [0402]
C7759  0.47uF  [0402]
CN1  0.1uF  [CAP_PACK_4_1206]
CN2  0.1uF  [CAP_PACK_4_1206]
CN3  0.1uF  [CAP_PACK_4_1206]
R13  1K  [0402]
R14  1K  [0402]
R15  1K  [0402]
R16  1K  [0402]
R17  1K  [0402]
R18  1K  [0402]
R19  1K  [0402]
R20  1K  [0402]
R21  1K  [0402]
R22  1K  [0402]
R23  1K  [0402]
R24  240  [0402]
R25  240  [0402]
R27  36  [0402]
R28  1K  [0402]
R29  DNI  [0402]
R30  1K  [0402]
R31  DNI  [0402]
R32  DNI  [0402]
R33  0  [0402]
R34  36  [0402]
R35  36  [0402]
R36  36  [0402]
R868  36  [0402]
R869  36  [0402]
R870  36  [0402]
R871  36  [0402]
R872  36  [0402]
R873  36  [0402]
R874  36  [0402]
R875  36  [0402]
R876  36  [0402]
R877  36  [0402]
R878  36  [0402]
R879  36  [0402]
R880  36  [0402]
R881  36  [0402]
R882  36  [0402]
R883  36  [0402]
R884  36  [0402]
R885  36  [0402]
R886  36  [0402]
R887  36  [0402]
R888  36  [0402]
R889  36  [0402]
R890  36  [0402]
R891  36  [0402]
U5  MT40A1G16KNR-075:E  [FBGA96]
sheet DDR4 CH0 Component 1
C1  0.1uF  [0402]
C2  0.1uF  [0402]
C3  0.47uF  [0402]
C4  0.47uF  [0402]
C5  22uF  [0603]
C6  0.47uF  [0402]
C7  0.47uF  [0402]
C8  22uF  [0603]
C9  2.2nF  [0402]
C10  2.2nF  [0402]
C11  2.2nF  [0402]
C12  2.2nF  [0402]
C13  2.2nF  [0402]
C14  2.2nF  [0402]
C15  2.2nF  [0402]
C16  2.2nF  [0402]
C17  2.2nF  [0402]
C18  3.3nF  [0402]
C19  3.3nF  [0402]
C20  4.7nF  [0402]
C21  4.7nF  [0402]
C22  4.7nF  [0402]
C23  0.47uF  [0402]
C24  0.47uF  [0402]
C25  0.47uF  [0402]
C26  22uF  [0603]
C27  22uF  [0603]
C28  1uF  [0402]
C29  1uF  [0402]
C30  0.01uF  [0402]
C31  0.01uF  [0402]
C32  0.01uF  [0402]
C33  0.1uF  [0402]
C34  0.1uF  [0402]
C35  0.1uF  [0402]
C36  0.1uF  [0402]
C37  0.47uF  [0402]
C38  0.47uF  [0402]
C39  0.47uF  [0402]
C40  0.47uF  [0402]
C41  0.47uF  [0402]
C42  0.47uF  [0402]
C43  0.47uF  [0402]
C44  0.47uF  [0402]
C45  0.47uF  [0402]
C46  0.47uF  [0402]
R1  240  [0402]
R2  240  [0402]
R3  240  [0402]
R4  240  [0402]
U1  MT40A1G16KNR-075:E  [FBGA96]
U2  MT40A1G16KNR-075:E  [FBGA96]
sheet DDR4 CH0 Component 2
C47  0.1uF  [0402]
C48  0.1uF  [0402]
C49  0.47uF  [0402]
C50  0.47uF  [0402]
C51  22uF  [0603]
C52  0.47uF  [0402]
C53  0.47uF  [0402]
C54  22uF  [0603]
C55  2.2nF  [0402]
C56  2.2nF  [0402]
C57  2.2nF  [0402]
C58  2.2nF  [0402]
C59  2.2nF  [0402]
C60  2.2nF  [0402]
C61  2.2nF  [0402]
C62  2.2nF  [0402]
C63  2.2nF  [0402]
C64  3.3nF  [0402]
C65  3.3nF  [0402]
C66  4.7nF  [0402]
C67  4.7nF  [0402]
C68  4.7nF  [0402]
C69  0.47uF  [0402]
C70  0.47uF  [0402]
C71  0.47uF  [0402]
C72  22uF  [0603]
C73  22uF  [0603]
C74  1uF  [0402]
C75  1uF  [0402]
C76  0.01uF  [0402]
C77  0.01uF  [0402]
C78  0.01uF  [0402]
C79  0.1uF  [0402]
C80  0.1uF  [0402]
C81  0.1uF  [0402]
C82  0.1uF  [0402]
C83  0.47uF  [0402]
C84  0.47uF  [0402]
C85  0.47uF  [0402]
C86  0.47uF  [0402]
C87  0.47uF  [0402]
C88  0.47uF  [0402]
C89  0.47uF  [0402]
C90  0.47uF  [0402]
C91  0.47uF  [0402]
C92  0.47uF  [0402]
R7  240  [0402]
R8  240  [0402]
R9  240  [0402]
R10  240  [0402]
U3  MT40A1G16KNR-075:E  [FBGA96]
U4  MT40A1G16KNR-075:E  [FBGA96]
sheet FPGA BANK 2F
U6  AgileX-I_2957A  [fbga2957a_hex_p56x45]  (sections A,B,C,D,E,F,G,H,I,J,K,L,M,N,O,P,Q,R,S,T,U,V,W,X,Y,Z)

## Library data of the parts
C1 C2 C33-C36 C79-C82 C93 = CAP: CAPC,  X7R, 0402, 0.1uF, 25V, ±20%; Item Num: K13660-001; LIFECYCLE_PHASE: Active; Lead Free Status: Lead Free; MFR_LIFECYCLE: Active; Manufacturer: Murata; Manufacturer Part Num: GRM155R71E104KE14D; Num Pins: 2; PART_SUBCLASS: CAPACITORS; Part Class: CAPACITORS; RATED_VOLTAGE: 25V; RoHS Compliant: RoHS Compliant; Tolerance: +80%/-20%
C3 C4 C6 C7 C23-C25 C37-C46 C49 C50 C52 C53 C69-C71 C83-C92 C94 C95 C7757-C7759 = CAP: CAP - CER, .47UF, 10V, X5R, 0402; AGILE_LINK: http://sj-agile9app/Agile/PLMServlet?action=OpenEmailObject&classid=10000&objid=256989651; Item Num: H75789-001; LIFECYCLE_PHASE: Active; Lead Free Status: Lead Free; MFR_LIFECYCLE: Active; Manufacturer: Murata; Manufacturer Part Num: GRM155R61A474KE15D; Num Pins: 2; PART_SUBCLASS: CAPACITORS; Part Class: CAPACITORS; RATED_VOLTAGE: 10V; RoHS Compliant: RoHS Compliant; Tolerance: +80%/-20%
C5 C8 C26 C27 C51 C54 C72 C73 C96 = CAP: CAP CER 22UF 6.3V X6S 0603; AGILE_LINK: http://sj-agile9app/Agile/PLMServlet?action=OpenEmailObject&classid=10000&objid=257560276; Item Num: H63299-001; LIFECYCLE_PHASE: Active; Lead Free Status: Not Lead Free; MFR_LIFECYCLE: Active; Manufacturer: Murata; Manufacturer Part Num: GRM188C80J226ME15D; Num Pins: 2; PART_SUBCLASS: CAPACITORS; RATED_VOLTAGE: 6.3V; RoHS Compliant: RoHS Compliant; TOLERANCE: 20%; Temperature Coefficient: X6S
C97 = CAP: CAP CER 100UF 6.3V X6T 1206; AGILE_LINK: http://sj-agile9app/Agile/PLMServlet?action=OpenEmailObject&classid=10000&objid=257560276; Isat: H65271-004; Item Num: H65271-004; LIFECYCLE_PHASE: Active; Lead Free Status: Lead Free; MFR_LIFECYCLE: Active; Manufacturer: Murata; Manufacturer Part Num: GRM31CR60J107ME39L; Num Pins: 2; PART_SUBCLASS: CAPACITORS; RATED_VOLTAGE: 6.3V; RoHS Compliant: RoHS Compliant; TOLERANCE: 20%; Temperature Coefficient: X6T
C30-C32 C76-C78 C98 = CAP: CAP, CER .01UF 16V X7R 0402; Item Num: A36096-007; Lead Free Status: No; Manufacturer: Murata; Manufacturer Part Num: GRM155R71C103KA01D; Manufacturer's Part No.: GRM155R71C103KA01D; Num Pins: 2; Part Class: CAPACITORS; Price: 0; RoHS Compliant: Yes
C7743-C7751 = CAP: CAP CER 2200PF 50V 10% X7R 0402; AGILE_LINK: http://sj-agile9app/Agile/PLMServlet?action=OpenEmailObject&classid=10000&objid=204246494; CAPACITANCE: 2200pF; Item Num: H63810-001; LIFECYCLE_PHASE: Active; Manufacturer: Murata; Manufacturer Part Num: GRM155R71H222KA01D; Num Pins: 2; PART_SUBCLASS: CAPACITORS; RATED_VOLTAGE: 50V; TOLERANCE: +/-10%
C18 C19 C64 C65 C7752 C7753 = CAP: CAP, CERAMIC, 3300PF, 10%, 50V, X7R, 0402; AGILE_LINK: http://sj-agile9app/Agile/PLMServlet?action=OpenEmailObject&classid=10000&objid=257002141; Item Num: K13754-001; LIFECYCLE_PHASE: Active; Lead Free Status: Lead Free; MFR_LIFECYCLE: Active; Manufacturer: Murata; Manufacturer Part Num: GRM155F51H332ZA01x; Num Pins: 2; PART_SUBCLASS: CAPACITORS; RATED_VOLTAGE: 50V; RoHS Compliant: RoHS Compliant; TOLERANCE: +/-10%
C20-C22 C66-C68 C7754-C7756 = CAP: CAP - CER 4700PF 50V 10% X7R 0402; AGILE_LINK: http://sj-agile9app/Agile/PLMServlet?action=OpenEmailObject&classid=10000&objid=215384813; Item Num: G24897-001; LIFECYCLE_PHASE: Active; Lead Free Status: Lead Free; MFR_LIFECYCLE: Active; Manufacturer: Murata; Manufacturer Part Num: GRM155R71H472KA01D; Num Pins: 2; PACKAGING: Tape & Reel (TR); PART_SUBCLASS: CAPACITORS; RATED_VOLTAGE: 50V; RoHS Compliant: RoHS Compliant; Supplier Part Num: GRM155R71H472KA01D; Tolerance: +/-10%
CN1-CN3 = CAP_ARRAY: CAPNET, 4 CAPS, CERAMIC, 0.1uF, 1206, 20%, 16VDC, X7R; Item Num: J41786-001; Manufacturer: Panasonic; Manufacturer Part Num: ECJ-RVB1C104M
R13-R23 R28-R32 = RESISTOR: RES,1.00K OHMS,1.0%,1/16W,0402; Item Num: G60609-021; Lead Free Status: No; Manufacturer: Panasonic; Manufacturer Part Num: ERJ-2RKF1001X; Num Pins: 2; Part Class: Resistors
R1-R4 R7-R10 R24 R25 = RESISTOR: RES - 240 OHM, 1/16W, 1%, 0402 SMD; Item Num: K15783-001; LIFECYCLE_PHASE: Active; Lead Free Status: Lead Free; MFR_LIFECYCLE: Active; Manufacturer: Panasonic; Manufacturer Part Num: ERJ-2RKF2400X; Num Pins: 2; PART_SUBCLASS: RESISTORS; RoHS Compliant: RoHS Compliant
R27 R34-R36 R868-R891 = RESISTOR: RES_D,0402,36.00OHM,1.00%,1/16W,; Item Num: A93548-623; Lead Free Status: Yes; Manufacturer: VISHAY; Manufacturer Part Num: CRCW040236R0FKED; Num Pins: 2; Part Class: Resistors; Price: 0
R33 = RES_0_OHM_5%_1_16W_0402_SMD: Item Num: H30887-001
U1-U5 = MT40A1G16HBA-083E_0: IC - Memory, 64M x 16 x 16 Banks x 1 Rank, 1.2V DDR4 SDRAM, TwinDie; Item Num: K20740-001; Manufacturer: Micron
C9-C17 C55-C63 = CAP: CAP CER 2200PF 50V 10% X7R 0402; AGILE_LINK: http://sj-agile9app/Agile/PLMServlet?action=OpenEmailObject&classid=10000&objid=204246494; CAPACITANCE: 2200pF; Item Num: A36096-022; LIFECYCLE_PHASE: Active; Manufacturer: Murata; Manufacturer Part Num: GRM155R71H222KA01D; Num Pins: 2; PART_SUBCLASS: CAPACITORS; RATED_VOLTAGE: 50V; TOLERANCE: +/-10%
C28 C29 C74 C75 = CAP: CAP - CER, 1uF, 10V, +/-10%, X5R, 0402; Item Num: G61001-001; Lead Free Status: Yes; Manufacturer: Murata; Manufacturer Part Num: GRM155R61A105KE15D; Num Pins: 2; Part Class: CAPACITORS; RoHS Compliant: Yes
C47 C48 = CAP: CAPC,  X7R, 0402, 0.1uF, 25V, ±20%; Dielectric: Y5V; Item Num: K13660-001; LIFECYCLE_PHASE: Active; Lead Free Status: Lead Free; MFR_LIFECYCLE: Active; Manufacturer: Murata; Manufacturer Part Num: GRM155R71E104KE14D; Num Pins: 2; PART_SUBCLASS: CAPACITORS; Part Class: CAPACITORS; RATED_VOLTAGE: 25V; RoHS Compliant: RoHS Compliant; Tolerance: +80%/-20%
U6 = AgileX-I_2957A: Item Num: 99C7VA

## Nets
GND: C1.2 C2.2 C3.2 C4.2 C5.1 C6.2 C7.2 C8.1 C9.2 C10.2 C11.2 C12.2 C13.2 C14.2 C15.2 C16.2 C17.2 C18.2 C19.2 C20.2 C21.2 C22.2 C23.2 C24.2 C25.2 C26.1 C27.1 C28.2 C29.2 C30.2 C31.2 C32.2 C33.2 C34.2 C35.2 C36.2 C37.2 C38.2 C39.2 C40.2 C41.2 C42.2 C43.2 C44.2 C45.2 C46.2 C47.2 C48.2 C49.2 C50.2 C51.1 C52.2 C53.2 C54.1 C55.2 C56.2 C57.2 C58.2 C59.2 C60.2 C61.2 C62.2 C63.2 C64.2 C65.2 C66.2 C67.2 C68.2 C69.2 C70.2 C71.2 C72.1 C73.1 C74.2 C75.2 C76.2 C77.2 C78.2 C79.2 C80.2 C81.2 C82.2 C83.2 C84.2 C85.2 C86.2 C87.2 C88.2 C89.2 C90.2 C91.2 C92.2 C93.2 C94.2 C95.2 C96.1 C97.1 C98.2 C7743.2 C7744.2 C7745.2 C7746.2 C7747.2 C7748.2 C7749.2 C7750.2 C7751.2 C7752.2 C7753.2 C7754.2 C7755.2 C7756.2 C7757.2 C7758.2 C7759.2 CN1.5 CN1.6 CN1.7 CN1.8 CN2.5 CN2.6 CN2.7 CN2.8 CN3.5 CN3.6 CN3.7 CN3.8 R1.2 R2.2 R3.2 R4.2 R7.2 R8.2 R9.2 R10.2 R13.1 R14.1 R15.1 R16.1 R17.1 R18.1 R19.1 R20.1 R21.1 R23.1 R24.2 R25.2 R30.1 R32.1 R33.2 U1.A2(VSSQ0) U1.A8(VSSQ1) U1.B2(VSS0) U1.C9(VSSQ2) U1.D2(VSSQ3) U1.D8(VSSQ4) U1.E1(VSS1) U1.E3(VSSQ5) U1.E8(VSSQ6) U1.F1(VSSQ7) U1.G8(VSS3) U1.H1(VSSQ8) U1.H9(VSSQ9) U1.K1(VSS4) U1.K9(VSS5) U1.N1(VSS6) U1.T1(VSS7) U1.T7(VSS2) U2.A2(VSSQ0) U2.A8(VSSQ1) U2.B2(VSS0) U2.C9(VSSQ2) U2.D2(VSSQ3) U2.D8(VSSQ4) U2.E1(VSS1) U2.E3(VSSQ5) U2.E8(VSSQ6) U2.F1(VSSQ7) U2.G8(VSS3) U2.H1(VSSQ8) U2.H9(VSSQ9) U2.K1(VSS4) U2.K9(VSS5) U2.N1(VSS6) U2.T1(VSS7) U2.T7(VSS2) U3.A2(VSSQ0) U3.A8(VSSQ1) U3.B2(VSS0) U3.C9(VSSQ2) U3.D2(VSSQ3) U3.D8(VSSQ4) U3.E1(VSS1) U3.E3(VSSQ5) U3.E8(VSSQ6) U3.F1(VSSQ7) U3.G8(VSS3) U3.H1(VSSQ8) U3.H9(VSSQ9) U3.K1(VSS4) U3.K9(VSS5) U3.N1(VSS6) U3.T1(VSS7) U3.T7(VSS2) U4.A2(VSSQ0) U4.A8(VSSQ1) U4.B2(VSS0) U4.C9(VSSQ2) U4.D2(VSSQ3) U4.D8(VSSQ4) U4.E1(VSS1) U4.E3(VSSQ5) U4.E8(VSSQ6) U4.F1(VSSQ7) U4.G8(VSS3) U4.H1(VSSQ8) U4.H9(VSSQ9) U4.K1(VSS4) U4.K9(VSS5) U4.N1(VSS6) U4.T1(VSS7) U4.T7(VSS2) U5.A2(VSSQ0) U5.A8(VSSQ1) U5.B2(VSS0) U5.C9(VSSQ2) U5.D2(VSSQ3) U5.D8(VSSQ4) U5.E1(VSS1) U5.E3(VSSQ5) U5.E8(VSSQ6) U5.F1(VSSQ7) U5.G8(VSS3) U5.H1(VSSQ8) U5.H9(VSSQ9) U5.K1(VSS4) U5.K9(VSS5) U5.N1(VSS6) U5.T1(VSS7) U5.T7(VSS2) ; also on sheet 13 14 15 16 17 18 19 20 21 22 23 25 26 27 28 29 30 31 32 33 34 35 36 38 39 40 41 42 43 44 45 46 47 48 49 50 51 52 53 54 55 56 57 58 59 60 61 62 63 64 65 66 67 68 69 70 71 72 73 74 75 76 77
0p6V_VREF_DDR4_CH01: C1.1 C2.1 C47.1 C48.1 C93.1 U1.M1(VREFCA) U2.M1(VREFCA) U3.M1(VREFCA) U4.M1(VREFCA) U5.M1(VREFCA) ; also on sheet 14 15 16 39 72 76
0p6V_VTT_DDR4_CH01: C97.2 CN1.1 CN1.2 CN1.3 CN1.4 CN2.1 CN2.2 CN2.3 CN2.4 CN3.1 CN3.2 CN3.3 CN3.4 R27.1 R34.2 R868.1 R869.1 R870.1 R871.1 R872.1 R873.1 R874.1 R875.1 R876.1 R877.1 R878.1 R879.1 R880.1 R881.1 R882.1 R883.1 R884.1 R885.1 R886.1 R887.1 R888.1 R889.1 R890.1 R891.1 ; also on sheet 16 72
1p2V_DDR4_CH01: C9.1 C10.1 C11.1 C12.1 C13.1 C14.1 C15.1 C16.1 C17.1 C18.1 C19.1 C20.1 C21.1 C22.1 C23.1 C24.1 C25.1 C26.2 C27.2 C28.1 C29.1 C30.1 C31.1 C32.1 C33.1 C34.1 C35.1 C36.1 C37.1 C38.1 C39.1 C40.1 C41.1 C42.1 C43.1 C44.1 C45.1 C46.1 C55.1 C56.1 C57.1 C58.1 C59.1 C60.1 C61.1 C62.1 C63.1 C64.1 C65.1 C66.1 C67.1 C68.1 C69.1 C70.1 C71.1 C72.2 C73.2 C74.1 C75.1 C76.1 C77.1 C78.1 C79.1 C80.1 C81.1 C82.1 C83.1 C84.1 C85.1 C86.1 C87.1 C88.1 C89.1 C90.1 C91.1 C92.1 C7743.1 C7744.1 C7745.1 C7746.1 C7747.1 C7748.1 C7749.1 C7750.1 C7751.1 C7752.1 C7753.1 C7754.1 C7755.1 C7756.1 C7757.1 C7758.1 C7759.1 R22.1 R28.1 R29.1 R31.1 U1.A1(VDDQ0) U1.A9(VDDQ1) U1.B3(VDD0) U1.B9(VDD1) U1.C1(VDDQ2) U1.D1(VDD2) U1.D9(VDDQ3) U1.F2(VDDQ4) U1.F8(VDDQ5) U1.G1(VDDQ6) U1.G7(VDD3) U1.G9(VDDQ7) U1.J1(VDD4) U1.J2(VDDQ8) U1.J8(VDDQ9) U1.J9(VDD5) U1.L1(VDD6) U1.L9(VDD7) U1.R1(VDD8) U1.T9(VDD9) U2.A1(VDDQ0) U2.A9(VDDQ1) U2.B3(VDD0) U2.B9(VDD1) U2.C1(VDDQ2) U2.D1(VDD2) U2.D9(VDDQ3) U2.F2(VDDQ4) U2.F8(VDDQ5) U2.G1(VDDQ6) U2.G7(VDD3) U2.G9(VDDQ7) U2.J1(VDD4) U2.J2(VDDQ8) U2.J8(VDDQ9) U2.J9(VDD5) U2.L1(VDD6) U2.L9(VDD7) U2.R1(VDD8) U2.T9(VDD9) U3.A1(VDDQ0) U3.A9(VDDQ1) U3.B3(VDD0) U3.B9(VDD1) U3.C1(VDDQ2) U3.D1(VDD2) U3.D9(VDDQ3) U3.F2(VDDQ4) U3.F8(VDDQ5) U3.G1(VDDQ6) U3.G7(VDD3) U3.G9(VDDQ7) U3.J1(VDD4) U3.J2(VDDQ8) U3.J8(VDDQ9) U3.J9(VDD5) U3.L1(VDD6) U3.L9(VDD7) U3.R1(VDD8) U3.T9(VDD9) U4.A1(VDDQ0) U4.A9(VDDQ1) U4.B3(VDD0) U4.B9(VDD1) U4.C1(VDDQ2) U4.D1(VDD2) U4.D9(VDDQ3) U4.F2(VDDQ4) U4.F8(VDDQ5) U4.G1(VDDQ6) U4.G7(VDD3) U4.G9(VDDQ7) U4.J1(VDD4) U4.J2(VDDQ8) U4.J8(VDDQ9) U4.J9(VDD5) U4.L1(VDD6) U4.L9(VDD7) U4.R1(VDD8) U4.T9(VDD9) U5.A1(VDDQ0) U5.A9(VDDQ1) U5.B3(VDD0) U5.B9(VDD1) U5.C1(VDDQ2) U5.D1(VDD2) U5.D9(VDDQ3) U5.F2(VDDQ4) U5.F8(VDDQ5) U5.G1(VDDQ6) U5.G7(VDD3) U5.G9(VDDQ7) U5.J1(VDD4) U5.J2(VDDQ8) U5.J8(VDDQ9) U5.J9(VDD5) U5.L1(VDD6) U5.L9(VDD7) U5.R1(VDD8) U5.T9(VDD9) ; also on sheet 14 15 16 32 39 46 47 52 70 72 76 77
2p5V: C3.1 C4.1 C5.2 C6.1 C7.1 C8.2 C49.1 C50.1 C51.2 C52.1 C53.1 C54.2 C94.1 C95.1 C96.2 U1.B1(VPP_2V5_0) U1.R9(VPP_2V5_1) U2.B1(VPP_2V5_0) U2.R9(VPP_2V5_1) U3.B1(VPP_2V5_0) U3.R9(VPP_2V5_1) U4.B1(VPP_2V5_0) U4.R9(VPP_2V5_1) U5.B1(VPP_2V5_0) U5.R9(VPP_2V5_1) ; also on sheet 14 15 16 19 20 43 45 46 73
CPU_1V2_RESETn: U6.KW57(IO,_CDR,_DIFF_RX_2B21N,_DQ38) ; also on sheet 52
DDR4_COMP_CH0_A0: R868.2 U1.P3(A0) U2.P3(A0) U3.P3(A0) U4.P3(A0) U5.P3(A0) ; also on sheet 23
DDR4_COMP_CH0_A1: R869.2 U1.P7(A1) U2.P7(A1) U3.P7(A1) U4.P7(A1) U5.P7(A1) ; also on sheet 23
DDR4_COMP_CH0_A2: R870.2 U1.R3(A2) U2.R3(A2) U3.R3(A2) U4.R3(A2) U5.R3(A2) ; also on sheet 23
DDR4_COMP_CH0_A3: R871.2 U1.N7(A3) U2.N7(A3) U3.N7(A3) U4.N7(A3) U5.N7(A3) ; also on sheet 23
DDR4_COMP_CH0_A4: R872.2 U1.N3(A4) U2.N3(A4) U3.N3(A4) U4.N3(A4) U5.N3(A4) ; also on sheet 23
DDR4_COMP_CH0_A5: R873.2 U1.P8(A5) U2.P8(A5) U3.P8(A5) U4.P8(A5) U5.P8(A5) ; also on sheet 23
DDR4_COMP_CH0_A6: R874.2 U1.P2(A6) U2.P2(A6) U3.P2(A6) U4.P2(A6) U5.P2(A6) ; also on sheet 23
DDR4_COMP_CH0_A7: R875.2 U1.R8(A7) U2.R8(A7) U3.R8(A7) U4.R8(A7) U5.R8(A7) ; also on sheet 23
DDR4_COMP_CH0_A8: R876.2 U1.R2(A8) U2.R2(A8) U3.R2(A8) U4.R2(A8) U5.R2(A8) ; also on sheet 23
DDR4_COMP_CH0_A9: R877.2 U1.R7(A9) U2.R7(A9) U3.R7(A9) U4.R7(A9) U5.R7(A9) ; also on sheet 23
DDR4_COMP_CH0_A10: R878.2 U1.M3(A10_AP) U2.M3(A10_AP) U3.M3(A10_AP) U4.M3(A10_AP) U5.M3(A10_AP) ; also on sheet 23
DDR4_COMP_CH0_A11: R879.2 U1.T2(A11) U2.T2(A11) U3.T2(A11) U4.T2(A11) U5.T2(A11) ; also on sheet 23
DDR4_COMP_CH0_A12: R880.2 U1.M7(A12_BC_n) U2.M7(A12_BC_n) U3.M7(A12_BC_n) U4.M7(A12_BC_n) U5.M7(A12_BC_n) ; also on sheet 23
DDR4_COMP_CH0_A13: R881.2 U1.T8(A13) U2.T8(A13) U3.T8(A13) U4.T8(A13) U5.T8(A13) ; also on sheet 23
DDR4_COMP_CH0_A14: R882.2 U1.L2(WE_n_A14) U2.L2(WE_n_A14) U3.L2(WE_n_A14) U4.L2(WE_n_A14) U5.L2(WE_n_A14) ; also on sheet 23
DDR4_COMP_CH0_A15: R883.2 U1.M8(CAS_n_A15) U2.M8(CAS_n_A15) U3.M8(CAS_n_A15) U4.M8(CAS_n_A15) U5.M8(CAS_n_A15) ; also on sheet 23
DDR4_COMP_CH0_A16: R884.2 U1.L8(RAS_n_A16) U2.L8(RAS_n_A16) U3.L8(RAS_n_A16) U4.L8(RAS_n_A16) U5.L8(RAS_n_A16) ; also on sheet 23
DDR4_COMP_CH0_ACT_N: R891.2 U1.L3(ACT_n) U2.L3(ACT_n) U3.L3(ACT_n) U4.L3(ACT_n) U5.L3(ACT_n) ; also on sheet 23
DDR4_COMP_CH0_ALERT_N: R28.2 U1.P9(ALERT_n) U2.P9(ALERT_n) U3.P9(ALERT_n) U4.P9(ALERT_n) U5.P9(ALERT_n) ; also on sheet 23
DDR4_COMP_CH0_BA0: R887.2 U1.N2(BA0) U2.N2(BA0) U3.N2(BA0) U4.N2(BA0) U5.N2(BA0) ; also on sheet 23
DDR4_COMP_CH0_BA1: R888.2 U1.N8(BA1) U2.N8(BA1) U3.N8(BA1) U4.N8(BA1) U5.N8(BA1) ; also on sheet 23
DDR4_COMP_CH0_BG0: R885.2 U1.M2(BG0) U2.M2(BG0) U3.M2(BG0) U4.M2(BG0) U5.M2(BG0) ; also on sheet 23
DDR4_COMP_CH0_BG1: R886.2 U1.M9(BG1) U2.M9(BG1) U3.M9(BG1) U4.M9(BG1) U5.M9(BG1) ; also on sheet 23
DDR4_COMP_CH0_CKE: R32.2 R34.1 U1.K2(CKE) U2.K2(CKE) U3.K2(CKE) U4.K2(CKE) U5.K2(CKE) ; also on sheet 23
DDR4_COMP_CH0_CLK_N: R36.2 U1.K8(CK_c) U2.K8(CK_c) U3.K8(CK_c) U4.K8(CK_c) U5.K8(CK_c) ; also on sheet 23
DDR4_COMP_CH0_CLK_P: R35.2 U1.K7(CK_t) U2.K7(CK_t) U3.K7(CK_t) U4.K7(CK_t) U5.K7(CK_t) ; also on sheet 23
DDR4_COMP_CH0_CS_N: R889.2 U1.L7(CS_n) U2.L7(CS_n) U3.L7(CS_n) U4.L7(CS_n) U5.L7(CS_n) ; also on sheet 23
DDR4_COMP_CH0_DBI_N0: U1.E7(NF_LDM_n_LDBI_n) ; also on sheet 23
DDR4_COMP_CH0_DBI_N1: U1.E2(NF_UDM_n_UDBI_n) ; also on sheet 23
DDR4_COMP_CH0_DBI_N2: U2.E7(NF_LDM_n_LDBI_n) ; also on sheet 24
DDR4_COMP_CH0_DBI_N3: U2.E2(NF_UDM_n_UDBI_n) ; also on sheet 24
DDR4_COMP_CH0_DBI_N4: U3.E7(NF_LDM_n_LDBI_n) ; also on sheet 23
DDR4_COMP_CH0_DBI_N5: U3.E2(NF_UDM_n_UDBI_n) ; also on sheet 23
DDR4_COMP_CH0_DBI_N6: U4.E7(NF_LDM_n_LDBI_n) ; also on sheet 24
DDR4_COMP_CH0_DBI_N7: U4.E2(NF_UDM_n_UDBI_n) ; also on sheet 24
DDR4_COMP_CH0_DBI_N8: U5.E7(NF_LDM_n_LDBI_n) ; also on sheet 23
DDR4_COMP_CH0_DQ0: U1.G2(DQ0) ; also on sheet 23
DDR4_COMP_CH0_DQ1: U1.F7(DQ1) ; also on sheet 23
DDR4_COMP_CH0_DQ2: U1.H3(DQ2) ; also on sheet 23
DDR4_COMP_CH0_DQ3: U1.H7(DQ3) ; also on sheet 23
DDR4_COMP_CH0_DQ4: U1.H2(DQ4) ; also on sheet 23
DDR4_COMP_CH0_DQ5: U1.H8(DQ5) ; also on sheet 23
DDR4_COMP_CH0_DQ6: U1.J3(DQ6) ; also on sheet 23
DDR4_COMP_CH0_DQ7: U1.J7(DQ7) ; also on sheet 23
DDR4_COMP_CH0_DQ8: U1.A3(DQ8) ; also on sheet 23
DDR4_COMP_CH0_DQ9: U1.B8(DQ9) ; also on sheet 23
DDR4_COMP_CH0_DQ10: U1.C3(DQ10) ; also on sheet 23
DDR4_COMP_CH0_DQ11: U1.C7(DQ11) ; also on sheet 23
DDR4_COMP_CH0_DQ12: U1.C2(DQ12) ; also on sheet 23
DDR4_COMP_CH0_DQ13: U1.C8(DQ13) ; also on sheet 23
DDR4_COMP_CH0_DQ14: U1.D3(DQ14) ; also on sheet 23
DDR4_COMP_CH0_DQ15: U1.D7(DQ15) ; also on sheet 23
DDR4_COMP_CH0_DQ16: U2.G2(DQ0) ; also on sheet 24
DDR4_COMP_CH0_DQ17: U2.F7(DQ1) ; also on sheet 24
DDR4_COMP_CH0_DQ18: U2.H3(DQ2) ; also on sheet 24
DDR4_COMP_CH0_DQ19: U2.H7(DQ3) ; also on sheet 24
DDR4_COMP_CH0_DQ20: U2.H2(DQ4) ; also on sheet 24
DDR4_COMP_CH0_DQ21: U2.H8(DQ5) ; also on sheet 24
DDR4_COMP_CH0_DQ22: U2.J3(DQ6) ; also on sheet 24
DDR4_COMP_CH0_DQ23: U2.J7(DQ7) ; also on sheet 24
DDR4_COMP_CH0_DQ24: U2.A3(DQ8) ; also on sheet 24
DDR4_COMP_CH0_DQ25: U2.B8(DQ9) ; also on sheet 24
DDR4_COMP_CH0_DQ26: U2.C3(DQ10) ; also on sheet 24
DDR4_COMP_CH0_DQ27: U2.C7(DQ11) ; also on sheet 24
DDR4_COMP_CH0_DQ28: U2.C2(DQ12) ; also on sheet 24
DDR4_COMP_CH0_DQ29: U2.C8(DQ13) ; also on sheet 24
DDR4_COMP_CH0_DQ30: U2.D3(DQ14) ; also on sheet 24
DDR4_COMP_CH0_DQ31: U2.D7(DQ15) ; also on sheet 24
DDR4_COMP_CH0_DQ32: U3.G2(DQ0) ; also on sheet 23
DDR4_COMP_CH0_DQ33: U3.F7(DQ1) ; also on sheet 23
DDR4_COMP_CH0_DQ34: U3.H3(DQ2) ; also on sheet 23
DDR4_COMP_CH0_DQ35: U3.H7(DQ3) ; also on sheet 23
DDR4_COMP_CH0_DQ36: U3.H2(DQ4) ; also on sheet 23
DDR4_COMP_CH0_DQ37: U3.H8(DQ5) ; also on sheet 23
DDR4_COMP_CH0_DQ38: U3.J3(DQ6) ; also on sheet 23
DDR4_COMP_CH0_DQ39: U3.J7(DQ7) ; also on sheet 23
DDR4_COMP_CH0_DQ40: U3.A3(DQ8) ; also on sheet 23
DDR4_COMP_CH0_DQ41: U3.B8(DQ9) ; also on sheet 23
DDR4_COMP_CH0_DQ42: U3.C3(DQ10) ; also on sheet 23
DDR4_COMP_CH0_DQ43: U3.C7(DQ11) ; also on sheet 23
DDR4_COMP_CH0_DQ44: U3.C2(DQ12) ; also on sheet 23
DDR4_COMP_CH0_DQ45: U3.C8(DQ13) ; also on sheet 23
DDR4_COMP_CH0_DQ46: U3.D3(DQ14) ; also on sheet 23
DDR4_COMP_CH0_DQ47: U3.D7(DQ15) ; also on sheet 23
DDR4_COMP_CH0_DQ48: U4.G2(DQ0) ; also on sheet 24
DDR4_COMP_CH0_DQ49: U4.F7(DQ1) ; also on sheet 24
DDR4_COMP_CH0_DQ50: U4.H3(DQ2) ; also on sheet 24
DDR4_COMP_CH0_DQ51: U4.H7(DQ3) ; also on sheet 24
DDR4_COMP_CH0_DQ52: U4.H2(DQ4) ; also on sheet 24
DDR4_COMP_CH0_DQ53: U4.H8(DQ5) ; also on sheet 24
DDR4_COMP_CH0_DQ54: U4.J3(DQ6) ; also on sheet 24
DDR4_COMP_CH0_DQ55: U4.J7(DQ7) ; also on sheet 24
DDR4_COMP_CH0_DQ56: U4.A3(DQ8) ; also on sheet 24
DDR4_COMP_CH0_DQ57: U4.B8(DQ9) ; also on sheet 24
DDR4_COMP_CH0_DQ58: U4.C3(DQ10) ; also on sheet 24
DDR4_COMP_CH0_DQ59: U4.C7(DQ11) ; also on sheet 24
DDR4_COMP_CH0_DQ60: U4.C2(DQ12) ; also on sheet 24
DDR4_COMP_CH0_DQ61: U4.C8(DQ13) ; also on sheet 24
DDR4_COMP_CH0_DQ62: U4.D3(DQ14) ; also on sheet 24
DDR4_COMP_CH0_DQ63: U4.D7(DQ15) ; also on sheet 24
DDR4_COMP_CH0_DQ64: U5.G2(DQ0) ; also on sheet 23
DDR4_COMP_CH0_DQ65: U5.F7(DQ1) ; also on sheet 23
DDR4_COMP_CH0_DQ66: U5.H3(DQ2) ; also on sheet 23
DDR4_COMP_CH0_DQ67: U5.H7(DQ3) ; also on sheet 23
DDR4_COMP_CH0_DQ68: U5.H2(DQ4) ; also on sheet 23
DDR4_COMP_CH0_DQ69: U5.H8(DQ5) ; also on sheet 23
DDR4_COMP_CH0_DQ70: U5.J3(DQ6) ; also on sheet 23
DDR4_COMP_CH0_DQ71: U5.J7(DQ7) ; also on sheet 23
DDR4_COMP_CH0_DQS_N0: U1.F3(LDQS_c) ; also on sheet 23
DDR4_COMP_CH0_DQS_N1: U1.A7(UDQS_c) ; also on sheet 23
DDR4_COMP_CH0_DQS_N2: U2.F3(LDQS_c) ; also on sheet 24
DDR4_COMP_CH0_DQS_N3: U2.A7(UDQS_c) ; also on sheet 24
DDR4_COMP_CH0_DQS_N4: U3.F3(LDQS_c) ; also on sheet 23
DDR4_COMP_CH0_DQS_N5: U3.A7(UDQS_c) ; also on sheet 23
DDR4_COMP_CH0_DQS_N6: U4.F3(LDQS_c) ; also on sheet 24
DDR4_COMP_CH0_DQS_N7: U4.A7(UDQS_c) ; also on sheet 24
DDR4_COMP_CH0_DQS_N8: U5.F3(LDQS_c) ; also on sheet 23
DDR4_COMP_CH0_DQS_P0: U1.G3(LDQS_t) ; also on sheet 23
DDR4_COMP_CH0_DQS_P1: U1.B7(UDQS_t) ; also on sheet 23
DDR4_COMP_CH0_DQS_P2: U2.G3(LDQS_t) ; also on sheet 24
DDR4_COMP_CH0_DQS_P3: U2.B7(UDQS_t) ; also on sheet 24
DDR4_COMP_CH0_DQS_P4: U3.G3(LDQS_t) ; also on sheet 23
DDR4_COMP_CH0_DQS_P5: U3.B7(UDQS_t) ; also on sheet 23
DDR4_COMP_CH0_DQS_P6: U4.G3(LDQS_t) ; also on sheet 24
DDR4_COMP_CH0_DQS_P7: U4.B7(UDQS_t) ; also on sheet 24
DDR4_COMP_CH0_DQS_P8: U5.G3(LDQS_t) ; also on sheet 23
DDR4_COMP_CH0_ODT: R890.2 U1.K3(ODT) U2.K3(ODT) U3.K3(ODT) U4.K3(ODT) U5.K3(ODT) ; also on sheet 23
DDR4_COMP_CH0_PAR: R27.2 U1.T3(PAR) U2.T3(PAR) U3.T3(PAR) U4.T3(PAR) U5.T3(PAR) ; also on sheet 23
DDR4_COMP_CH0_RESET_N: R29.2 R30.2 U1.P1(RESET_n) U2.P1(RESET_n) U3.P1(RESET_n) U4.P1(RESET_n) U5.P1(RESET_n) ; also on sheet 23
DDR4_COMP_CH0_TEN: R31.2 R33.1 U1.N9(TEN_VSS) U2.N9(TEN_VSS) U3.N9(TEN_VSS) U4.N9(TEN_VSS) U5.N9(TEN_VSS)
DDR4_DDIMM2_DBI_N0: U6.LR57(IO,_DIFF_RX_2B5P,_DQ33) ; also on sheet 19
DDR4_DDIMM2_DBI_N2: U6.KF52(IO,_DIFF_RX_2B23P,_DQ39) ; also on sheet 19
DDR4_DDIMM2_DBI_N5: U6.MD60(IO,_DIFF_RX_2B2P,_DQ32) ; also on sheet 19
DDR4_DDIMM2_DBI_N6: U6.MD54(IO,_PLL_2B_T_CLKOUT0P,_PLL_2B_T_CLKOUT0,_PLL_2B_T_FB0,_DIFF_RX_2B8P,_DQ34) ; also on sheet 19
DDR4_DDIMM2_DBI_N7: U6.LB52(IO,_DIFF_RX_2B11P,_DQ35) ; also on sheet 19
DDR4_DDIMM2_DQ0: U6.LN56(IO,_RZQ_T_2B,_CDR,_DIFF_RX_2B6P,_DQ33) ; also on sheet 19
DDR4_DDIMM2_DQ1: U6.MA56(IO,_CLK_T_2B_1P,_DIFF_TX_2B6P,_DQ33) ; also on sheet 19
DDR4_DDIMM2_DQ2: U6.LW55(IO,_CLK_T_2B_1N,_DIFF_TX_2B6N,_DQ33) ; also on sheet 19
DDR4_DDIMM2_DQ3: U6.LR55(IO,_CDR,_DIFF_RX_2B6N,_DQ33) ; also on sheet 19
DDR4_DDIMM2_DQ4: U6.LN60(IO,_DIFF_RX_2B4N,_DQ33) ; also on sheet 19
DDR4_DDIMM2_DQ5: U6.MA60(IO,_DIFF_TX_2B4P,_DQ33) ; also on sheet 19
DDR4_DDIMM2_DQ6: U6.LW59(IO,_DIFF_TX_2B4N,_DQ33) ; also on sheet 19
DDR4_DDIMM2_DQ7: U6.LR59(IO,_DIFF_RX_2B4P,_DQ33) ; also on sheet 19
DDR4_DDIMM2_DQ16: U6.KF50(IO,_CDR,_DIFF_RX_2B24P,_DQ39) ; also on sheet 19
DDR4_DDIMM2_DQ17: U6.KJ51(IO,_CDR,_DIFF_RX_2B24N,_DQ39) ; also on sheet 19
DDR4_DDIMM2_DQ18: U6.KU50(IO,_DIFF_TX_2B24N,_DQ39) ; also on sheet 19
DDR4_DDIMM2_DQ19: U6.KR51(IO,_DIFF_TX_2B24P,_DQ39) ; also on sheet 19
DDR4_DDIMM2_DQ20: U6.KJ55(IO,_CDR,_DIFF_RX_2B22P,_DQ39) ; also on sheet 19
DDR4_DDIMM2_DQ21: U6.KR55(IO,_DIFF_TX_2B22N,_DQ39) ; also on sheet 19
DDR4_DDIMM2_DQ22: U6.KU54(IO,_DIFF_TX_2B22P,_DQ39) ; also on sheet 19
DDR4_DDIMM2_DQ23: U6.KF54(IO,_CDR,_DIFF_RX_2B22N,_DQ39) ; also on sheet 19
DDR4_DDIMM2_DQ40: U6.MK59(IO,_DIFF_TX_2B3P,_DQ32) ; also on sheet 19
DDR4_DDIMM2_DQ41: U6.MH58(IO,_DIFF_TX_2B3N,_DQ32) ; also on sheet 19
DDR4_DDIMM2_DQ42: U6.MC59(IO,_CDR,_DIFF_RX_2B3P,_DQ32) ; also on sheet 19
DDR4_DDIMM2_DQ43: U6.MD58(IO,_CDR,_DIFF_RX_2B3N,_DQ32) ; also on sheet 19
DDR4_DDIMM2_DQ44: U6.MK63(IO,_DIFF_TX_2B1P,_DQ32) ; also on sheet 19
DDR4_DDIMM2_DQ45: U6.MC63(IO,_DIFF_RX_2B1N,_DQ32) ; also on sheet 19
DDR4_DDIMM2_DQ46: U6.MH62(IO,_DIFF_TX_2B1N,_DQ32) ; also on sheet 19
DDR4_DDIMM2_DQ47: U6.MD62(IO,_DIFF_RX_2B1P,_DQ32) ; also on sheet 19
DDR4_DDIMM2_DQ48: U6.MC53(IO,_CDR,_DIFF_RX_2B9P,_DQ34) ; also on sheet 19
DDR4_DDIMM2_DQ49: U6.MK53(IO,_DIFF_TX_2B9P,_DQ34) ; also on sheet 19
DDR4_DDIMM2_DQ50: U6.MH52(IO,_DIFF_TX_2B9N,_DQ34) ; also on sheet 19
DDR4_DDIMM2_DQ51: U6.MD52(IO,_CDR,_DIFF_RX_2B9N,_DQ34) ; also on sheet 19
DDR4_DDIMM2_DQ52: U6.MH56(IO,_DIFF_TX_2B7N,_DQ34) ; also on sheet 19
DDR4_DDIMM2_DQ53: U6.MC57(IO,_CLK_T_2B_0N,_DIFF_RX_2B7N,_DQ34) ; also on sheet 19
DDR4_DDIMM2_DQ54: U6.MK57(IO,_DIFF_TX_2B7P,_DQ34) ; also on sheet 19
DDR4_DDIMM2_DQ55: U6.MD56(IO,_CLK_T_2B_0P,_DIFF_RX_2B7P,_DQ34) ; also on sheet 19
DDR4_DDIMM2_DQ56: U6.LL51(IO,_DIFF_TX_2B12P,_DQ35) ; also on sheet 19
DDR4_DDIMM2_DQ57: U6.KW51(IO,_CDR,_DIFF_RX_2B12P,_DQ35) ; also on sheet 19
DDR4_DDIMM2_DQ58: U6.LB50(IO,_CDR,_DIFF_RX_2B12N,_DQ35) ; also on sheet 19
DDR4_DDIMM2_DQ59: U6.LH50(IO,_DIFF_TX_2B12N,_DQ35) ; also on sheet 19
DDR4_DDIMM2_DQ60: U6.LL55(IO,_DIFF_TX_2B10P,_DQ35) ; also on sheet 19
DDR4_DDIMM2_DQ61: U6.KW55(IO,_DIFF_RX_2B10N,_DQ35) ; also on sheet 19
DDR4_DDIMM2_DQ62: U6.LH54(IO,_DIFF_TX_2B10N,_DQ35) ; also on sheet 19
DDR4_DDIMM2_DQ63: U6.LB54(IO,_DIFF_RX_2B10P,_DQ35) ; also on sheet 19
DDR4_DDIMM2_DQS_N0: U6.MA58(IO,_PLL_2B_T_CLKOUT1N,_DIFF_TX_2B5N,_DQSN33) ; also on sheet 19
DDR4_DDIMM2_DQS_N2: U6.KR53(IO,_DIFF_TX_2B23N,_DQSN39) ; also on sheet 19
DDR4_DDIMM2_DQS_N5: U6.MK61(IO,_DIFF_TX_2B2N,_DQSN32) ; also on sheet 19
DDR4_DDIMM2_DQS_N6: U6.MK55(IO,_DIFF_TX_2B8N,_DQSN34) ; also on sheet 19
DDR4_DDIMM2_DQS_N7: U6.LL53(IO,_DIFF_TX_2B11N,_DQSN35) ; also on sheet 19
DDR4_DDIMM2_DQS_P0: U6.LW57(IO,_PLL_2B_T_CLKOUT1P,_PLL_2B_T_CLKOUT1,_PLL_2B_T_FB1,_DIFF_TX_2B5P,_DQS33) ; also on sheet 19
DDR4_DDIMM2_DQS_P2: U6.KU52(IO,_DIFF_TX_2B23P,_DQS39) ; also on sheet 19
DDR4_DDIMM2_DQS_P5: U6.MH60(IO,_DIFF_TX_2B2P,_DQS32) ; also on sheet 19
DDR4_DDIMM2_DQS_P6: U6.MH54(IO,_DIFF_TX_2B8P,_DQS34) ; also on sheet 19
DDR4_DDIMM2_DQS_P7: U6.LH52(IO,_DIFF_TX_2B11P,_DQS35) ; also on sheet 19
DDR4_DDIMM2_TDQS_N9: U6.LN58(IO,_DIFF_RX_2B5N,_DQ33) ; also on sheet 19
DDR4_DDIMM2_TDQS_N11: U6.KJ53(IO,_DIFF_RX_2B23N,_DQ39) ; also on sheet 19
DDR4_DDIMM2_TDQS_N14: U6.MC61(IO,_DIFF_RX_2B2N,_DQ32) ; also on sheet 19
DDR4_DDIMM2_TDQS_N15: U6.MC55(IO,_PLL_2B_T_CLKOUT0N,_DIFF_RX_2B8N,_DQ34) ; also on sheet 19
DDR4_DDIMM2_TDQS_N16: U6.KW53(IO,_DIFF_RX_2B11N,_DQ35) ; also on sheet 19
FPGA_DIMM2_EVENT_N: U6.KJ59(IO,_DIFF_RX_2B17N,_DQ37) ; also on sheet 19
FPGA_DIMM2_SAVE_N: U6.KR59(IO,_PLL_2B_B_CLKOUT1N,_DIFF_TX_2B17N,_DQSN37) ; also on sheet 19
FPGA_I2C1_SCL: U6.KJ61(IO,_CDR,_DIFF_RX_2B16P,_DQ37) ; also on sheet 46
FPGA_I2C1_SDA: U6.KF60(IO,_CDR,_DIFF_RX_2B16N,_DQ37) ; also on sheet 46
M10_1V2_CLK: U6.LB60(IO,_CLK_B_2B_0P,_CDR,_DIFF_RX_2B19P,_DQ38) ; also on sheet 52
M10_1V2_DATA0: U6.LH60(IO,_DIFF_TX_2B19N,_DQ38) ; also on sheet 52
M10_1V2_DATA1: U6.LL61(IO,_DIFF_TX_2B19P,_DQ38) ; also on sheet 52
M10_1V2_DATA2: U6.KW59(IO,_PLL_2B_B_CLKOUT0N,_DIFF_RX_2B20N,_DQ38) ; also on sheet 52
M10_1V2_DATA3: U6.LB58(IO,_PLL_2B_B_CLKOUT0P,_PLL_2B_B_CLKOUT0,_PLL_2B_B_FB0,_DIFF_RX_2B20P,_DQ38) ; also on sheet 52
M10_1V2_GPIO0: U6.LL59(IO,_DIFF_TX_2B20N,_DQSN38) ; also on sheet 52
M10_1V2_GPIO1: U6.LH58(IO,_DIFF_TX_2B20P,_DQS38) ; also on sheet 52
M10_1V2_SSN: U6.KW61(IO,_CLK_B_2B_0N,_CDR,_DIFF_RX_2B19N,_DQ38) ; also on sheet 52
N28015562: R1.1 U1.F9(ZQ0)
N28022993: R2.1 U2.F9(ZQ0)
N30715060: R7.1 U3.F9(ZQ0)
N30715756: R8.1 U4.F9(ZQ0)
N31558092: R3.1 U1.E9(ZQ1)
N31558448: R4.1 U2.E9(ZQ1)
N31558945: R9.1 U3.E9(ZQ1)
N31559300: R10.1 U4.E9(ZQ1)
N39077807: C98.1 R35.1 R36.1
N39077887: R24.1 U5.F9(ZQ0)
N39077990: R13.2 U5.A3(DQ8)
N39077991: R14.2 U5.B8(DQ9)
N39077992: R15.2 U5.C3(DQ10)
N39077993: R16.2 U5.C7(DQ11)
N39077994: R17.2 U5.C2(DQ12)
N39077995: R18.2 U5.C8(DQ13)
N39077996: R19.2 U5.D3(DQ14)
N39077997: R20.2 U5.D7(DQ15)
N39078014: R21.2 U5.E2(NF_UDM_n_UDBI_n)
N39078018: R22.2 U5.B7(UDQS_t)
N39078019: R23.2 U5.A7(UDQS_c)
N39078023: R25.1 U5.E9(ZQ1)

Not connected (* = marked no-connect by the designer): U6 KF56(IO,_RZQ_B_2B,_CDR,_DIFF_RX_2B18P,_DQ37)* KF58(IO,_DIFF_RX_2B17P,_DQ37)* KJ57(IO,_CDR,_DIFF_RX_2B18N,_DQ37)* KR57(IO,_CLK_B_2B_1N,_DIFF_TX_2B18N,_DQ37)* KR61(IO,_DIFF_TX_2B16N,_DQ37)* KU56(IO,_CLK_B_2B_1P,_DIFF_TX_2B18P,_DQ37)* KU58(IO,_PLL_2B_B_CLKOUT1P,_PLL_2B_B_CLKOUT1,_PLL_2B_B_FB1,_DIFF_TX_2B17P,_DQS37)* KU60(IO,_DIFF_TX_2B16P,_DQ37)* LB56(IO,_CDR,_DIFF_RX_2B21P,_DQ38)* LH56(IO,_DIFF_TX_2B21N,_DQ38)* LL57(IO,_DIFF_TX_2B21P,_DQ38)*

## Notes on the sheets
sheet 1
- REV
- DATE
- PAGES
- DESCRIPTION
- A0
- 07/14/2020
- All
- Initial
- A1
- 27/04/2022
- All
- Changed Enpirion parts with ADI parts
- B1
- 28/07/2022
- Page 67
- U117: Updated PGOOD connection
- C
- 22/03/2024
- All
- REVISION UPDATE & U6,U24,U25 PNS ARE UPDATED
- SPEED Item
- RAW PCB
- M76625-004
- PAGE
- DESCRIPTION
- PAGE
- DESCRIPTION
- PBA BOM  ( FM67 )
- M17471-100
- 1
- Title, Notes, Rev. History
- 39
- FPGA Power 3
- 2
- Block Diagram
- 40
- FPGA GND1
- PBA BOM  ( FM85 )
- N24193-001
- Schematic Design File
- 100-0330695-C
- 3
- Power Tree Diagram
- 41
- FPGA GND2
- 4
- Power Sequence Diagram
- 42
- FPGA GND3
- 5
- Clock Tree Diagram
- 43
- Clock 1
- 6
- I2C Diagram
- 44
- Clock 2
- 7
- JTAG Diagram
- 45
- Clock 3
- 8
- DDR4_DDR4 Pin Map
- 46
- I2C and PMBUS
- 9
- DDR4 CH0 Component 1
- 47
- LEDs for QDFPDD
- 10
- DDR4 CH0 Component 2
- 48
- LEDs, Pushbutton And IOEXP
- 11
- DDR4 CH0 Comp Termination
- 49
- System MAX10 1
- 12
- FPGA BANK 2B
- 50
- System MAX10 2
- 13
- FPGA BANK 2E
- 51
- System MAX10 3
- 14
- DDR4 CH1 Component 1
- 52
- Level Shifter
- 15
- DDR4 CH1 Component 2
- 53
- Power inputs
- 16
- DDR4 CH1 Comp Termination
- 54
- PWR - VCC- 1
- 17
- FPGA BANK 2C
- 55
- PWR - VCC- 2
- 18
- FPGA BANK 2F
- 56
- PWR - VCC- 3
- 19
- DDR4/DDRT DIMM-A
- 57
- PWR - 12V to 5V
- 20
- DDR4/DDRT DIMM-B
- 58
- PWR - 12V to 3.3V
- 21
- FPGA BANK 3D
- 59
- PWR - VCCR_CORE
- 22
- FPGA BANK 3C
- 60
- PWR - VCCED_GXR
- 23
- FPGA BANK 3A
- 61
- PWR - VCCERT_FGT_GXF
- 24
- FPGA BANK 3B
- 62
- PWR - VCCRT_GXR
- 25
- QSFPDD0
- 63
- PWR - VCC_HSSI_GXR
- 26
- QSFPDD1
- 64
- PWR - VCCH
- 27
- QSFPDD IO
- 65
- PWR - VCC_HSSI_GXF
- 28
- FPGA BANK 12A
- 66
- PWR - 1p8V
- 29
- FPGA BANK 12A DNU
- 67
- Blank
- 30
- PCIe EP Edge Connector
- 68
- PWR - IO_1p8V
- 31
- FPGA BANK 14C
- 69
- PWR - 1p2V_PRE
- 32
- CXL Connector
- 70
- PWR - VCCEHT_GXF
- 33
- FPGA BANK 15C
- 71
- PWR - 1p2V_DDR4_CH01
- 34
- FPGA BANK 15A
- 72
- PWR - 1p2V_DDR4_CH2
- 35
- FPGA BANK CONFIG SDM
- 73
- PWR - 0p6V_VTT/VREF
- 36
- FPGA BANK HPS
- 74
- PWR - 2p5V
- 37
- FPGA Power 1
- 75
- PWR - VCCCLK_GXR
- 38
- FPGA Power 2
- 76
- Decoupling Caps 1
- 77
- Decoupling Caps 2
sheet 4
- Power Sequence Diagram
sheet 5
- Clock Tree
sheet 6
- I2C Diagram
sheet 7
- JTAG Block Diagrram
sheet 8
- DDR4/DDR-T DIMM Pin Map
- DDR-T DIMM Pin Map is Identical
  to standard DDR4 DIMM Pin Map
  except the DDR-T protocol
  repurposes five of these pins:
- CS1# (pin 89) : Grant, GNT# <0>  Input
- CKE1 (pin 203) : Request, REQ# <0> Output
- ODT1 (pin 91) : Error, ERR#      Output
- CLK1 (pin 218):Early Read ID, ERID<0>  Output
- CLK1# (pin 219):Early Read ID, ERID<1>  Output
sheet 9
- DDR4 COMPONENT #1/#2
sheet 10
- DDR4 COMPONENT #3/#4
sheet 11
- DDR4 COMPONENT #5 & Termination
sheet 12
- DDR4/T DIMM CH1  INTERFACE -- FPGA SIDE 2B
